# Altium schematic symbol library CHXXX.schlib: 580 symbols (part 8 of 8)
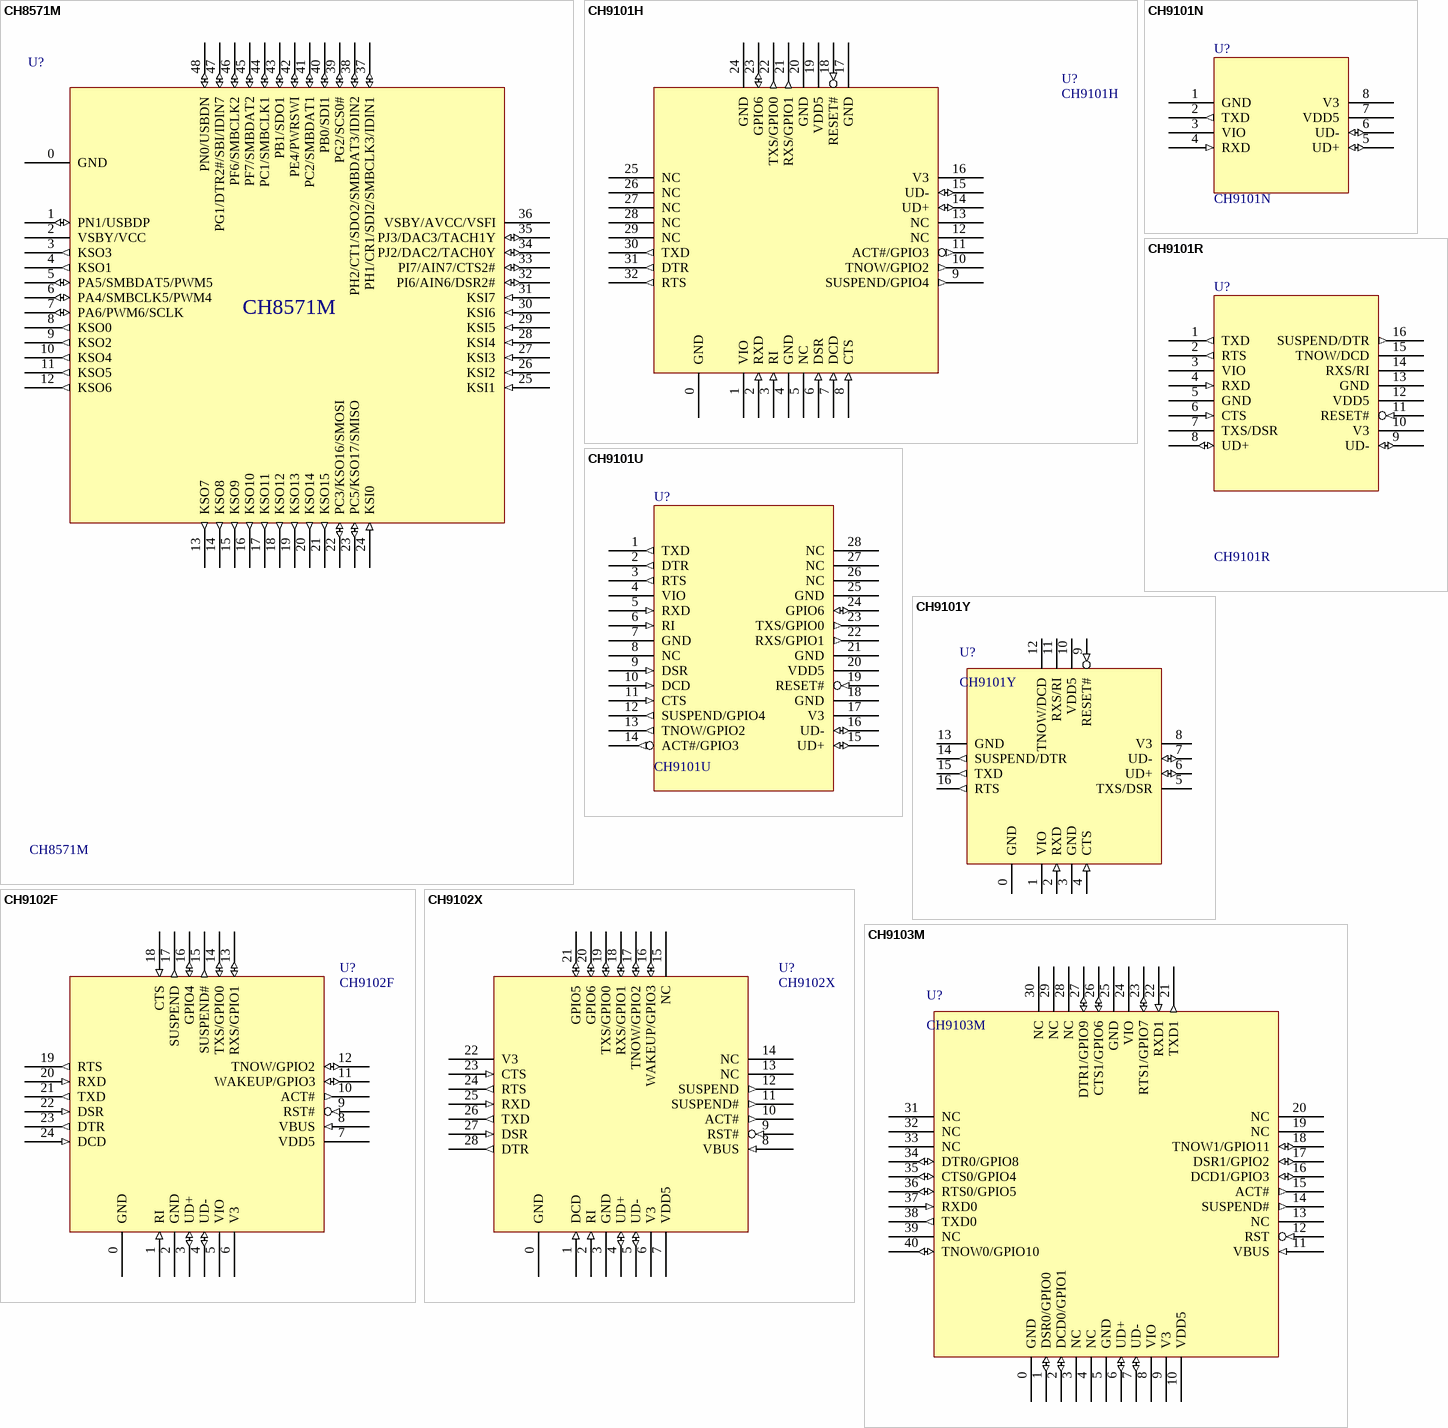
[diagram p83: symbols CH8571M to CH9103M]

## CH9102F
designator U?
USB to high speed TTL Serial / UART
footprint QFN24_4X4
pins: 0 GND (power), 1 RI (in), 2 GND (power), 3 UD+ (io), 4 UD- (io), 5 VIO (power), 6 V3 (power), 7 VDD5 (power), 8 VBUS (in), 9 RST# (in), 10 ACT# (out), 11 WAKEUP/GPIO3 (io), 12 TNOW/GPIO2 (io), 13 RXS/GPIO1 (io), 14 TXS/GPIO0 (io), 15 SUSPEND# (out), 16 GPIO4 (io), 17 SUSPEND (out), 18 CTS (in), 19 RTS (out), 20 RXD (in), 21 TXD (out), 22 DSR (in), 23 DTR (out), 24 DCD (in)

## CH9102X
designator U?
USB to high speed TTL Serial / UART
footprint QFN28_5X5
pins: 0 GND (power), 1 DCD (in), 2 RI (in), 3 GND (power), 4 UD+ (io), 5 UD- (io), 6 V3 (power), 7 VDD5 (power), 8 VBUS (in), 9 RST# (in), 10 ACT# (out), 11 SUSPEND# (out), 12 SUSPEND (out), 13 NC, 14 NC, 15 NC, 16 WAKEUP/GPIO3 (io), 17 TNOW/GPIO2 (io), 18 RXS/GPIO1 (io), 19 TXS/GPIO0 (io), 20 GPIO6 (io), 21 GPIO5 (io), 22 V3 (power), 23 CTS (in), 24 RTS (out), 25 RXD (in), 26 TXD (out), 27 DSR (in), 28 DTR (out)

## CH9103M
designator U?
USB to dual enhanced TTL Serial / 2*UART
footprint QFN40_6X6
pins: 0 GND (power), 1 DSR0/GPIO0 (io), 2 DCD0/GPIO1 (io), 3 NC, 4 NC, 5 GND (power), 6 UD+ (io), 7 UD- (io), 8 VIO (power), 9 V3 (power), 10 VDD5 (power), 11 VBUS (in), 12 RST (in), 13 NC, 14 SUSPEND# (out), 15 ACT# (out), 16 DCD1/GPIO3 (io), 17 DSR1/GPIO2 (io), 18 TNOW1/GPIO11 (io), 19 NC, 20 NC, 21 TXD1 (out), 22 RXD1 (in), 23 RTS1/GPIO7 (io), 24 VIO (power), 25 GND (power), 26 CTS1/GPIO6 (io), 27 DTR1/GPIO9 (io), 28 NC, 29 NC, 30 NC, 31 NC, 32 NC, 33 NC, 34 DTR0/GPIO8 (io), 35 CTS0/GPIO4 (io), 36 RTS0/GPIO5 (io), 37 RXD0 (in), 38 TXD0 (out), 39 NC, 40 TNOW0/GPIO10 (io)

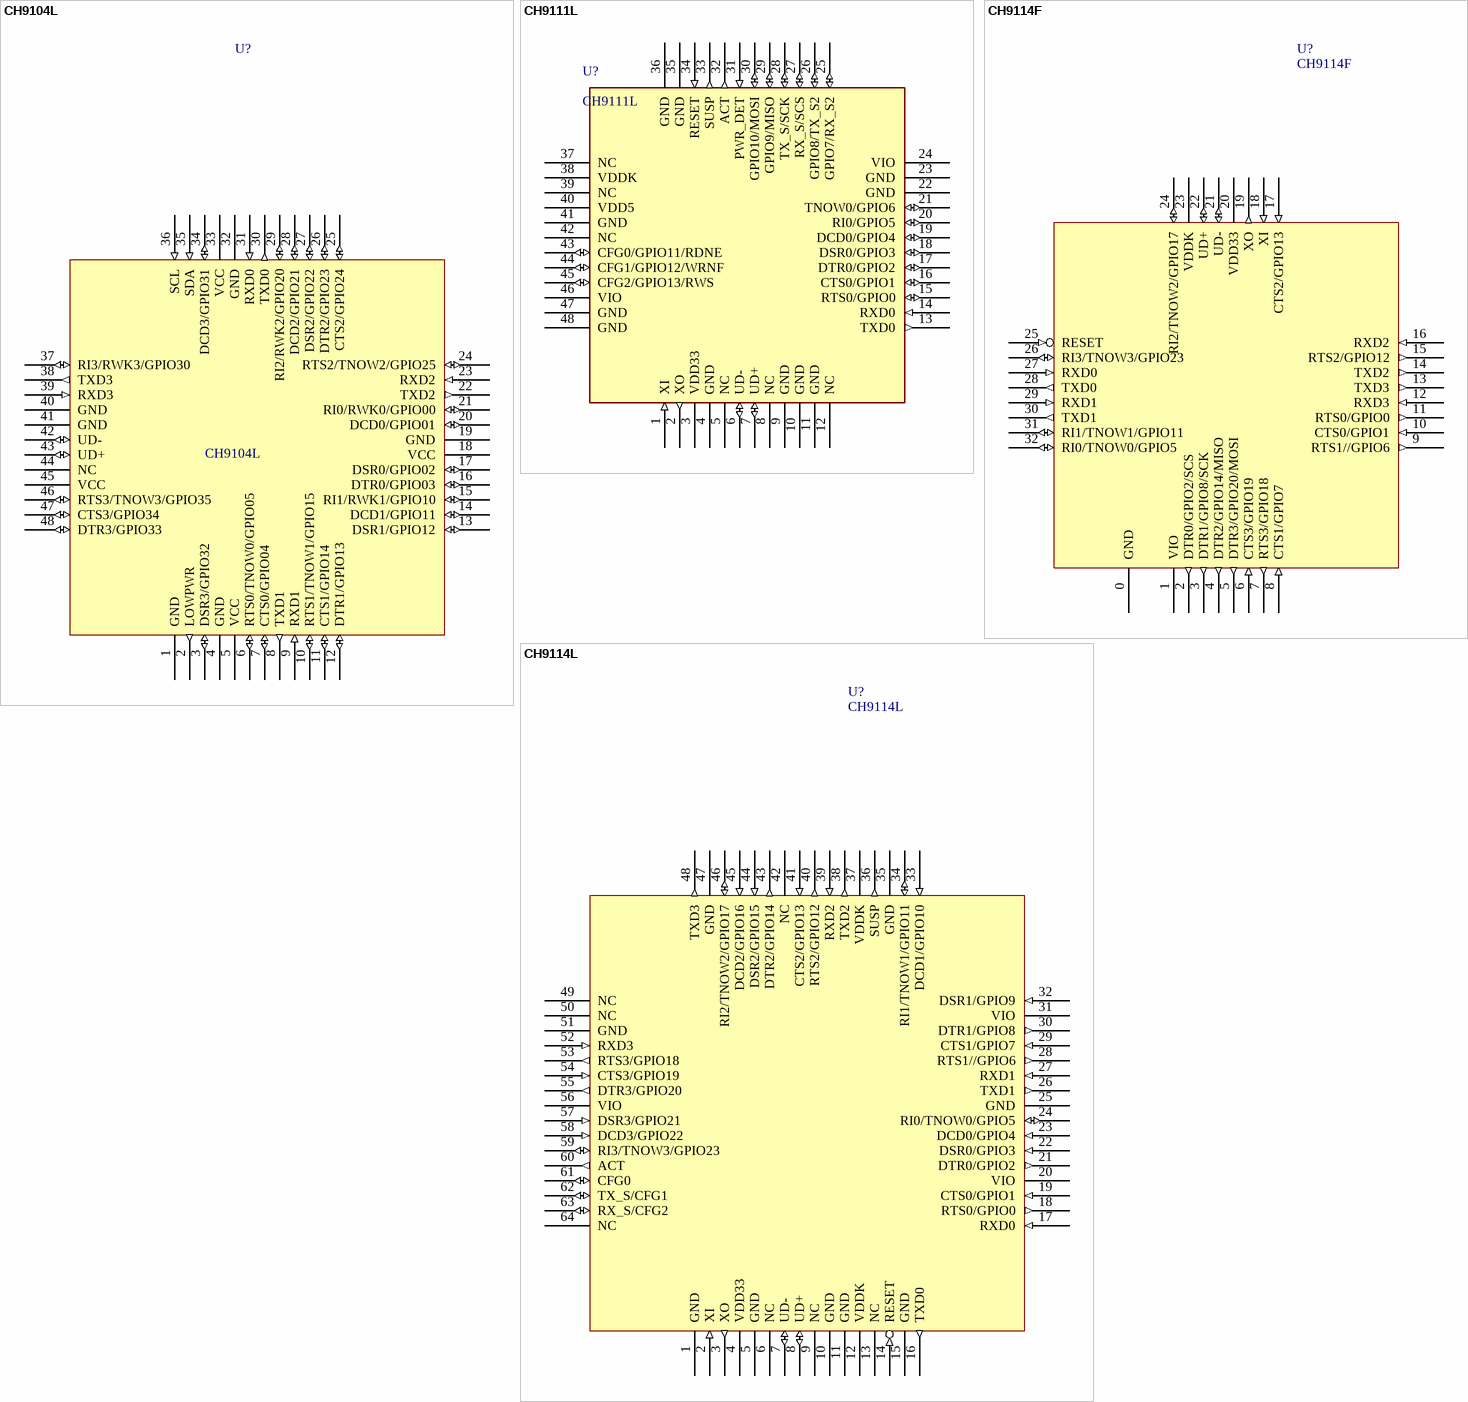
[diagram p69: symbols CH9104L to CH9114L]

## CH9104L
designator U?
USB to quad serial ports / 4*UART
footprint TQFP48_7X7
pins: 1 GND (power), 2 LOWPWR (out), 3 DSR3/GPIO32 (io), 4 GND (power), 5 VCC (power), 6 RTS0/TNOW0/GPIO05 (io), 7 CTS0/GPIO04 (io), 8 TXD1 (out), 9 RXD1 (in), 10 RTS1/TNOW1/GPIO15 (io), 11 CTS1/GPIO14 (io), 12 DTR1/GPIO13 (io), 13 DSR1/GPIO12 (io), 14 DCD1/GPIO11 (io), 15 RI1/RWK1/GPIO10 (io), 16 DTR0/GPIO03 (io), 17 DSR0/GPIO02 (io), 18 VCC (power), 19 GND (power), 20 DCD0/GPIO01 (io), 21 RI0/RWK0/GPIO00 (io), 22 TXD2 (out), 23 RXD2 (in), 24 RTS2/TNOW2/GPIO25 (io), 25 CTS2/GPIO24 (io), 26 DTR2/GPIO23 (io), 27 DSR2/GPIO22 (io), 28 DCD2/GPIO21 (io), 29 RI2/RWK2/GPIO20 (io), 30 TXD0 (out), 31 RXD0 (in), 32 GND (power), 33 VCC (power), 34 DCD3/GPIO31 (io), 35 SDA (in), 36 SCL (in), 37 RI3/RWK3/GPIO30 (io), 38 TXD3 (out), 39 RXD3 (in), 40 GND (power), 41 GND (power), 42 UD- (io), 43 UD+ (io), 44 NC, 45 VCC (power), 46 RTS3/TNOW3/GPIO35 (io), 47 CTS3/GPIO34 (io), 48 DTR3/GPIO33 (io)

## CH9111L
designator U?
High Speed USB to UART
footprint QFN48_7X7
pins: 1 XI (in), 2 XO (out), 3 VDD33 (power), 4 GND (power), 5 NC, 6 UD- (io), 7 UD+ (io), 8 NC, 9 GND (power), 10 GND (power), 11 GND (power), 12 NC, 13 TXD0 (out), 14 RXD0 (in), 15 RTS0/GPIO0 (io), 16 CTS0/GPIO1 (io), 17 DTR0/GPIO2 (io), 18 DSR0/GPIO3 (io), 19 DCD0/GPIO4 (io), 20 RI0/GPIO5 (io), 21 TNOW0/GPIO6 (io), 22 GND (power), 23 GND (power), 24 VIO (power), 25 GPIO7/RX_S2 (io), 26 GPIO8/TX_S2 (io), 27 RX_S/SCS (io), 28 TX_S/SCK (io), 29 GPIO9/MISO (io), 30 GPIO10/MOSI (io), 31 PWR_DET (in), 32 ACT (out), 33 SUSP (out), 34 RESET (in), 35 GND (power), 36 GND (power), 37 NC, 38 VDDK (power), 39 NC, 40 VDD5 (power), 41 GND (power), 42 NC, 43 CFG0/GPIO11/RDNE (io), 44 CFG1/GPIO12/WRNF (io), 45 CFG2/GPIO13/RWS (io), 46 VIO (power), 47 GND (power), 48 GND (power)

## CH9114F
designator U?
high-speed USB to quad UART & SPI
footprint QFN32_4X4
pins: 0 GND (power), 1 VIO (power), 2 DTR0/GPIO2/SCS (out), 3 DTR1/GPIO8/SCK (out), 4 DTR2/GPIO14/MISO (out), 5 DTR3/GPIO20/MOSI (out), 6 CTS3/GPIO19 (in), 7 RTS3/GPIO18 (out), 8 CTS1/GPIO7 (in), 9 RTS1//GPIO6 (out), 10 CTS0/GPIO1 (in), 11 RTS0/GPIO0 (out), 12 RXD3 (in), 13 TXD3 (out), 14 TXD2 (out), 15 RTS2/GPIO12 (out), 16 RXD2 (in), 17 CTS2/GPIO13 (in), 18 XI (in), 19 XO (out), 20 VDD33 (power), 21 UD- (io), 22 UD+ (io), 23 VDDK (power), 24 RI2/TNOW2/GPIO17 (io), 25 RESET (in), 26 RI3/TNOW3/GPIO23 (io), 27 RXD0 (in), 28 TXD0 (out), 29 RXD1 (in), 30 TXD1 (out), 31 RI1/TNOW1/GPIO11 (io), 32 RI0/TNOW0/GPIO5 (io)

## CH9114L
designator U?
high-speed USB to quad UART & dual SPI
footprint LQFP64M_10X10
pins: 1 GND (power), 2 XI (in), 3 XO (out), 4 VDD33 (power), 5 GND (power), 6 NC, 7 UD- (io), 8 UD+ (io), 9 NC, 10 GND (power), 11 GND (power), 12 VDDK (power), 13 NC, 14 RESET (in), 15 GND (power), 16 TXD0 (out), 17 RXD0 (in), 18 RTS0/GPIO0 (out), 19 CTS0/GPIO1 (in), 20 VIO (power), 21 DTR0/GPIO2 (out), 22 DSR0/GPIO3 (in), 23 DCD0/GPIO4 (in), 24 RI0/TNOW0/GPIO5 (io), 25 GND (power), 26 TXD1 (out), 27 RXD1 (in), 28 RTS1//GPIO6 (out), 29 CTS1/GPIO7 (in), 30 DTR1/GPIO8 (out), 31 VIO (power), 32 DSR1/GPIO9 (in), 33 DCD1/GPIO10 (in), 34 RI1/TNOW1/GPIO11 (io), 35 GND (power), 36 SUSP (out), 37 VDDK (power), 38 TXD2 (out), 39 RXD2 (in), 40 RTS2/GPIO12 (out), 41 CTS2/GPIO13 (in), 42 NC, 43 DTR2/GPIO14 (out), 44 DSR2/GPIO15 (in), 45 DCD2/GPIO16 (in), 46 RI2/TNOW2/GPIO17 (io), 47 GND (power), 48 TXD3 (out), 49 NC, 50 NC, 51 GND (power), 52 RXD3 (in), 53 RTS3/GPIO18 (out), 54 CTS3/GPIO19 (in), 55 DTR3/GPIO20 (out), 56 VIO (power), 57 DSR3/GPIO21 (in), 58 DCD3/GPIO22 (in), 59 RI3/TNOW3/GPIO23 (io), 60 ACT (out), 61 CFG0 (io), 62 TX_S/CFG1 (io), 63 RX_S/CFG2 (io), 64 NC

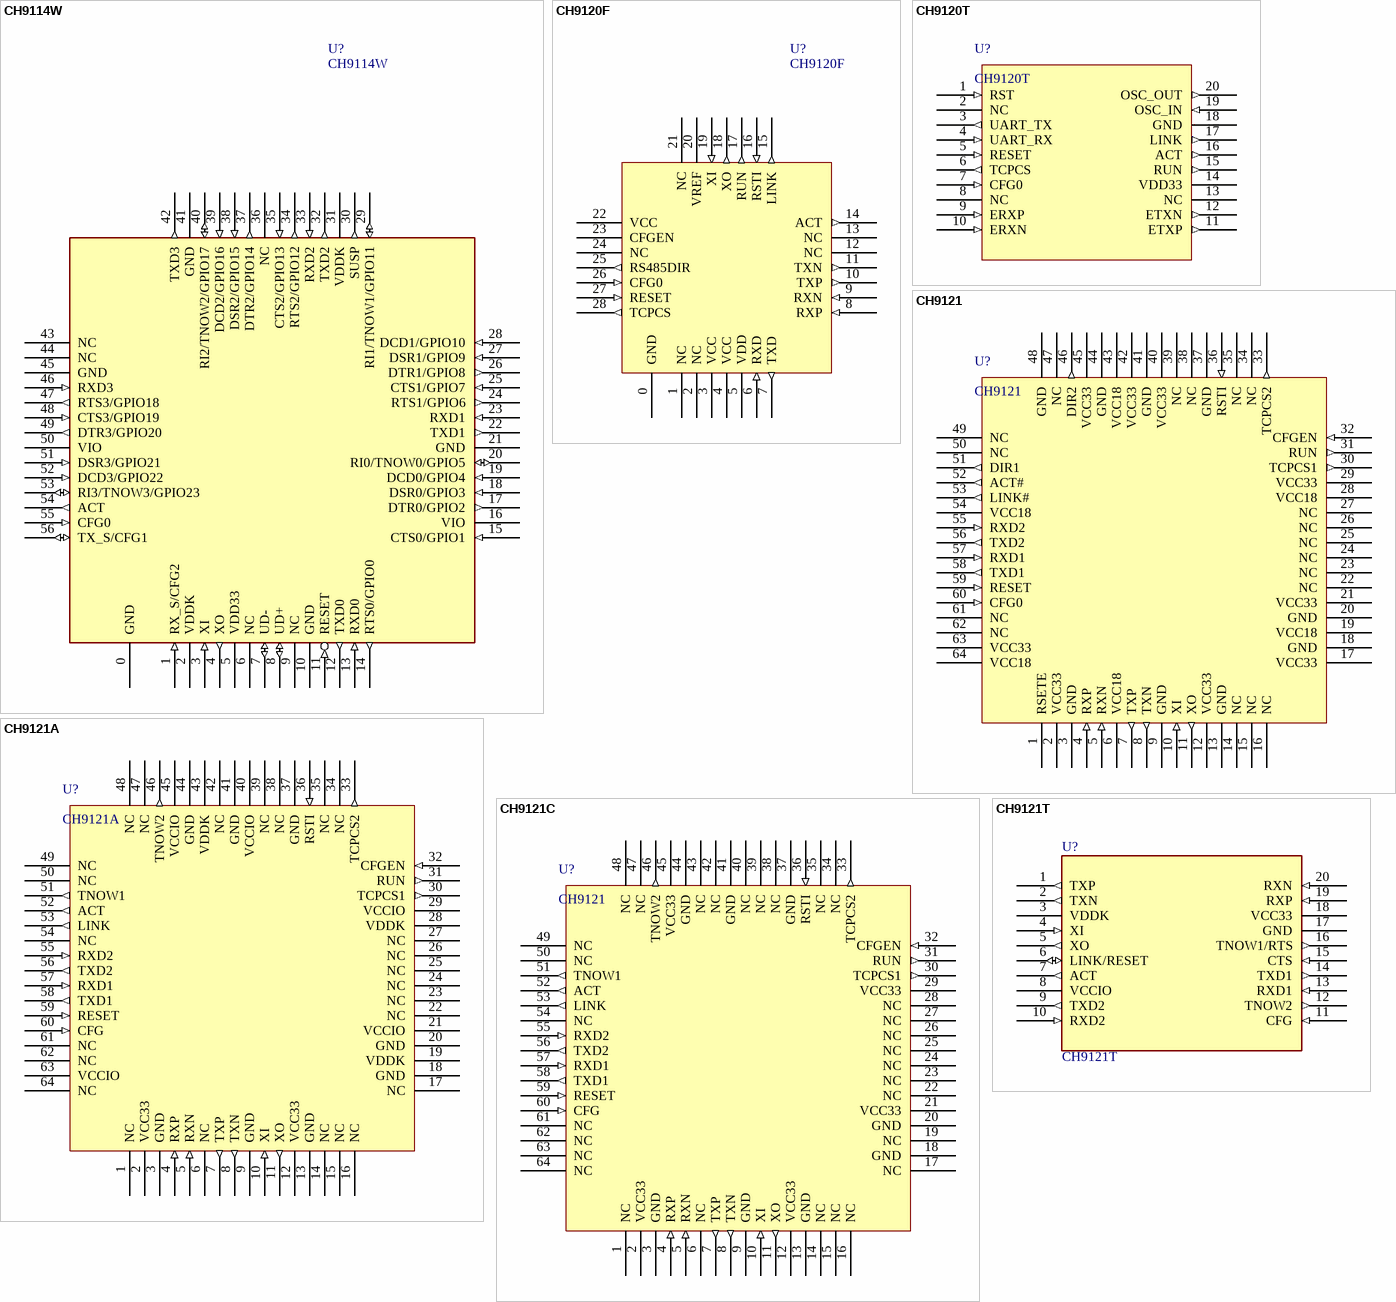
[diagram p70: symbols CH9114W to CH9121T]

## CH9114W
designator U?
high-speed USB to quad UART & dual SPI
footprint QFN56_8X8
pins: 0 GND (power), 1 RX_S/CFG2 (in), 2 VDDK (power), 3 XI (in), 4 XO (out), 5 VDD33 (power), 6 NC, 7 UD- (io), 8 UD+ (io), 9 NC, 10 GND (power), 11 RESET (in), 12 TXD0 (out), 13 RXD0 (in), 14 RTS0/GPIO0 (out), 15 CTS0/GPIO1 (in), 16 VIO (power), 17 DTR0/GPIO2 (out), 18 DSR0/GPIO3 (in), 19 DCD0/GPIO4 (in), 20 RI0/TNOW0/GPIO5 (io), 21 GND (power), 22 TXD1 (out), 23 RXD1 (in), 24 RTS1/GPIO6 (out), 25 CTS1/GPIO7 (in), 26 DTR1/GPIO8 (out), 27 DSR1/GPIO9 (in), 28 DCD1/GPIO10 (in), 29 RI1/TNOW1/GPIO11 (io), 30 SUSP (out), 31 VDDK (power), 32 TXD2 (out), 33 RXD2 (in), 34 RTS2/GPIO12 (out), 35 CTS2/GPIO13 (in), 36 NC, 37 DTR2/GPIO14 (out), 38 DSR2/GPIO15 (in), 39 DCD2/GPIO16 (in), 40 RI2/TNOW2/GPIO17 (io), 41 GND (power), 42 TXD3 (out), 43 NC, 44 NC, 45 GND (power), 46 RXD3 (in), 47 RTS3/GPIO18 (out), 48 CTS3/GPIO19 (in), 49 DTR3/GPIO20 (out), 50 VIO (power), 51 DSR3/GPIO21 (in), 52 DCD3/GPIO22 (in), 53 RI3/TNOW3/GPIO23 (io), 54 ACT (out), 55 CFG0 (in), 56 TX_S/CFG1 (io)

## CH9120F
designator U?
TTL serail / UART to 10Mbps ethernet
footprint QFN28_4X4
pins: 0 GND (power), 1 NC, 2 NC, 3 VCC (power), 4 VCC (power), 5 VDD (power), 6 RXD (in), 7 TXD (out), 8 RXP (in), 9 RXN (in), 10 TXP (out), 11 TXN (out), 12 NC, 13 NC, 14 ACT (out), 15 LINK (out), 16 RSTI (in), 17 RUN (out), 18 XO (out), 19 XI (in), 20 VREF (power), 21 NC, 22 VCC (power), 23 CFGEN, 24 NC, 25 RS485DIR (out), 26 CFG0 (in), 27 RESET (in), 28 TCPCS (out)

## CH9120T
designator U?
TTL serail / UART to 10Mbps ethernet
footprint TSSOP20
pins: 1 RST (in), 2 NC, 3 UART_TX (out), 4 UART_RX (in), 5 RESET (in), 6 TCPCS (out), 7 CFG0 (in), 8 NC, 9 ERXP (in), 10 ERXN (in), 11 ETXP (out), 12 ETXN (out), 13 NC, 14 VDD33 (power), 15 RUN (out), 16 ACT (out), 17 LINK (out), 18 GND (power), 19 OSC_IN (in), 20 OSC_OUT (out)

## CH9121
designator U?
dual TTL serail / 2*UART to 10Mbps/100Mbps Ethernet
footprint LQFP64M_10X10
pins: 1 RSETE, 2 VCC33 (power), 3 GND, 4 RXP (in), 5 RXN (in), 6 VCC18 (power), 7 TXP (out), 8 TXN (out), 9 GND (power), 10 XI (in), 11 XO (out), 12 VCC33 (power), 13 GND (power), 14 NC, 15 NC, 16 NC, 17 VCC33 (power), 18 GND (power), 19 VCC18 (power), 20 GND (power), 21 VCC33 (power), 22 NC, 23 NC, 24 NC, 25 NC, 26 NC, 27 NC, 28 VCC18 (power), 29 VCC33 (power), 30 TCPCS1 (out), 31 RUN (out), 32 CFGEN (in), 33 TCPCS2 (out), 34 NC, 35 NC, 36 RSTI (in), 37 GND (power), 38 NC, 39 NC, 40 VCC33 (power), 41 GND (power), 42 VCC33 (power), 43 VCC18 (power), 44 GND (power), 45 VCC33 (power), 46 DIR2 (out), 47 NC, 48 GND (power), 49 NC, 50 NC, 51 DIR1 (out), 52 ACT# (out), 53 LINK# (out), 54 VCC18 (power), 55 RXD2 (in), 56 TXD2 (out), 57 RXD1 (in), 58 TXD1 (out), 59 RESET (in), 60 CFG0 (in), 61 NC, 62 NC, 63 VCC33 (power), 64 VCC18 (power)

## CH9121A
designator U?
dual TTL serail / 2*UART to 10Mbps/100Mbps Ethernet
footprint LQFP64M_10X10
pins: 1 NC, 2 VCC33 (power), 3 GND, 4 RXP (in), 5 RXN (in), 6 NC (power), 7 TXP (out), 8 TXN (out), 9 GND (power), 10 XI (in), 11 XO (out), 12 VCC33 (power), 13 GND (power), 14 NC, 15 NC, 16 NC, 17 NC (power), 18 GND (power), 19 VDDK (power), 20 GND (power), 21 VCCIO (power), 22 NC, 23 NC, 24 NC, 25 NC, 26 NC, 27 NC, 28 VDDK (power), 29 VCCIO (power), 30 TCPCS1 (out), 31 RUN (out), 32 CFGEN (in), 33 TCPCS2 (out), 34 NC, 35 NC, 36 RSTI (in), 37 GND (power), 38 NC, 39 NC, 40 VCCIO (power), 41 GND (power), 42 NC (power), 43 VDDK (power), 44 GND (power), 45 VCCIO (power), 46 TNOW2 (out), 47 NC, 48 NC (power), 49 NC, 50 NC, 51 TNOW1 (out), 52 ACT (out), 53 LINK (out), 54 NC (power), 55 RXD2 (in), 56 TXD2 (out), 57 RXD1 (in), 58 TXD1 (out), 59 RESET (in), 60 CFG (in), 61 NC, 62 NC, 63 VCCIO (power), 64 NC (power)

## CH9121C
designator U?, comment CH9121
dual TTL serail / 2*UART to 10Mbps/100Mbps Ethernet
footprint LQFP64M_10X10
pins: 1 NC, 2 VCC33 (power), 3 GND, 4 RXP (in), 5 RXN (in), 6 NC, 7 TXP (out), 8 TXN (out), 9 GND (power), 10 XI (in), 11 XO (out), 12 VCC33 (power), 13 GND (power), 14 NC, 15 NC, 16 NC, 17 NC (power), 18 GND (power), 19 NC (power), 20 GND (power), 21 VCC33 (power), 22 NC, 23 NC, 24 NC, 25 NC, 26 NC, 27 NC, 28 NC, 29 VCC33 (power), 30 TCPCS1 (out), 31 RUN (out), 32 CFGEN (in), 33 TCPCS2 (out), 34 NC, 35 NC, 36 RSTI (in), 37 GND (power), 38 NC, 39 NC, 40 NC, 41 GND (power), 42 NC (power), 43 NC, 44 GND (power), 45 VCC33 (power), 46 TNOW2 (out), 47 NC, 48 NC (power), 49 NC, 50 NC, 51 TNOW1 (out), 52 ACT (out), 53 LINK (out), 54 NC (power), 55 RXD2 (in), 56 TXD2 (out), 57 RXD1 (in), 58 TXD1 (out), 59 RESET (in), 60 CFG (in), 61 NC, 62 NC, 63 NC, 64 NC (power)

## CH9121T
designator U?
Network and UART Transparent Transmission on 100M Ethernet
footprint TSSOP20
pins: 1 TXP (out), 2 TXN (out), 3 VDDK, 4 XI (in), 5 XO (out), 6 LINK/RESET (io), 7 ACT (out), 8 VCCIO, 9 TXD2 (out), 10 RXD2 (in), 11 CFG (in), 12 TNOW2 (out), 13 RXD1 (in), 14 TXD1 (out), 15 CTS (in), 16 TNOW1/RTS (out), 17 GND, 18 VCC33, 19 RXP (in), 20 RXN (in)

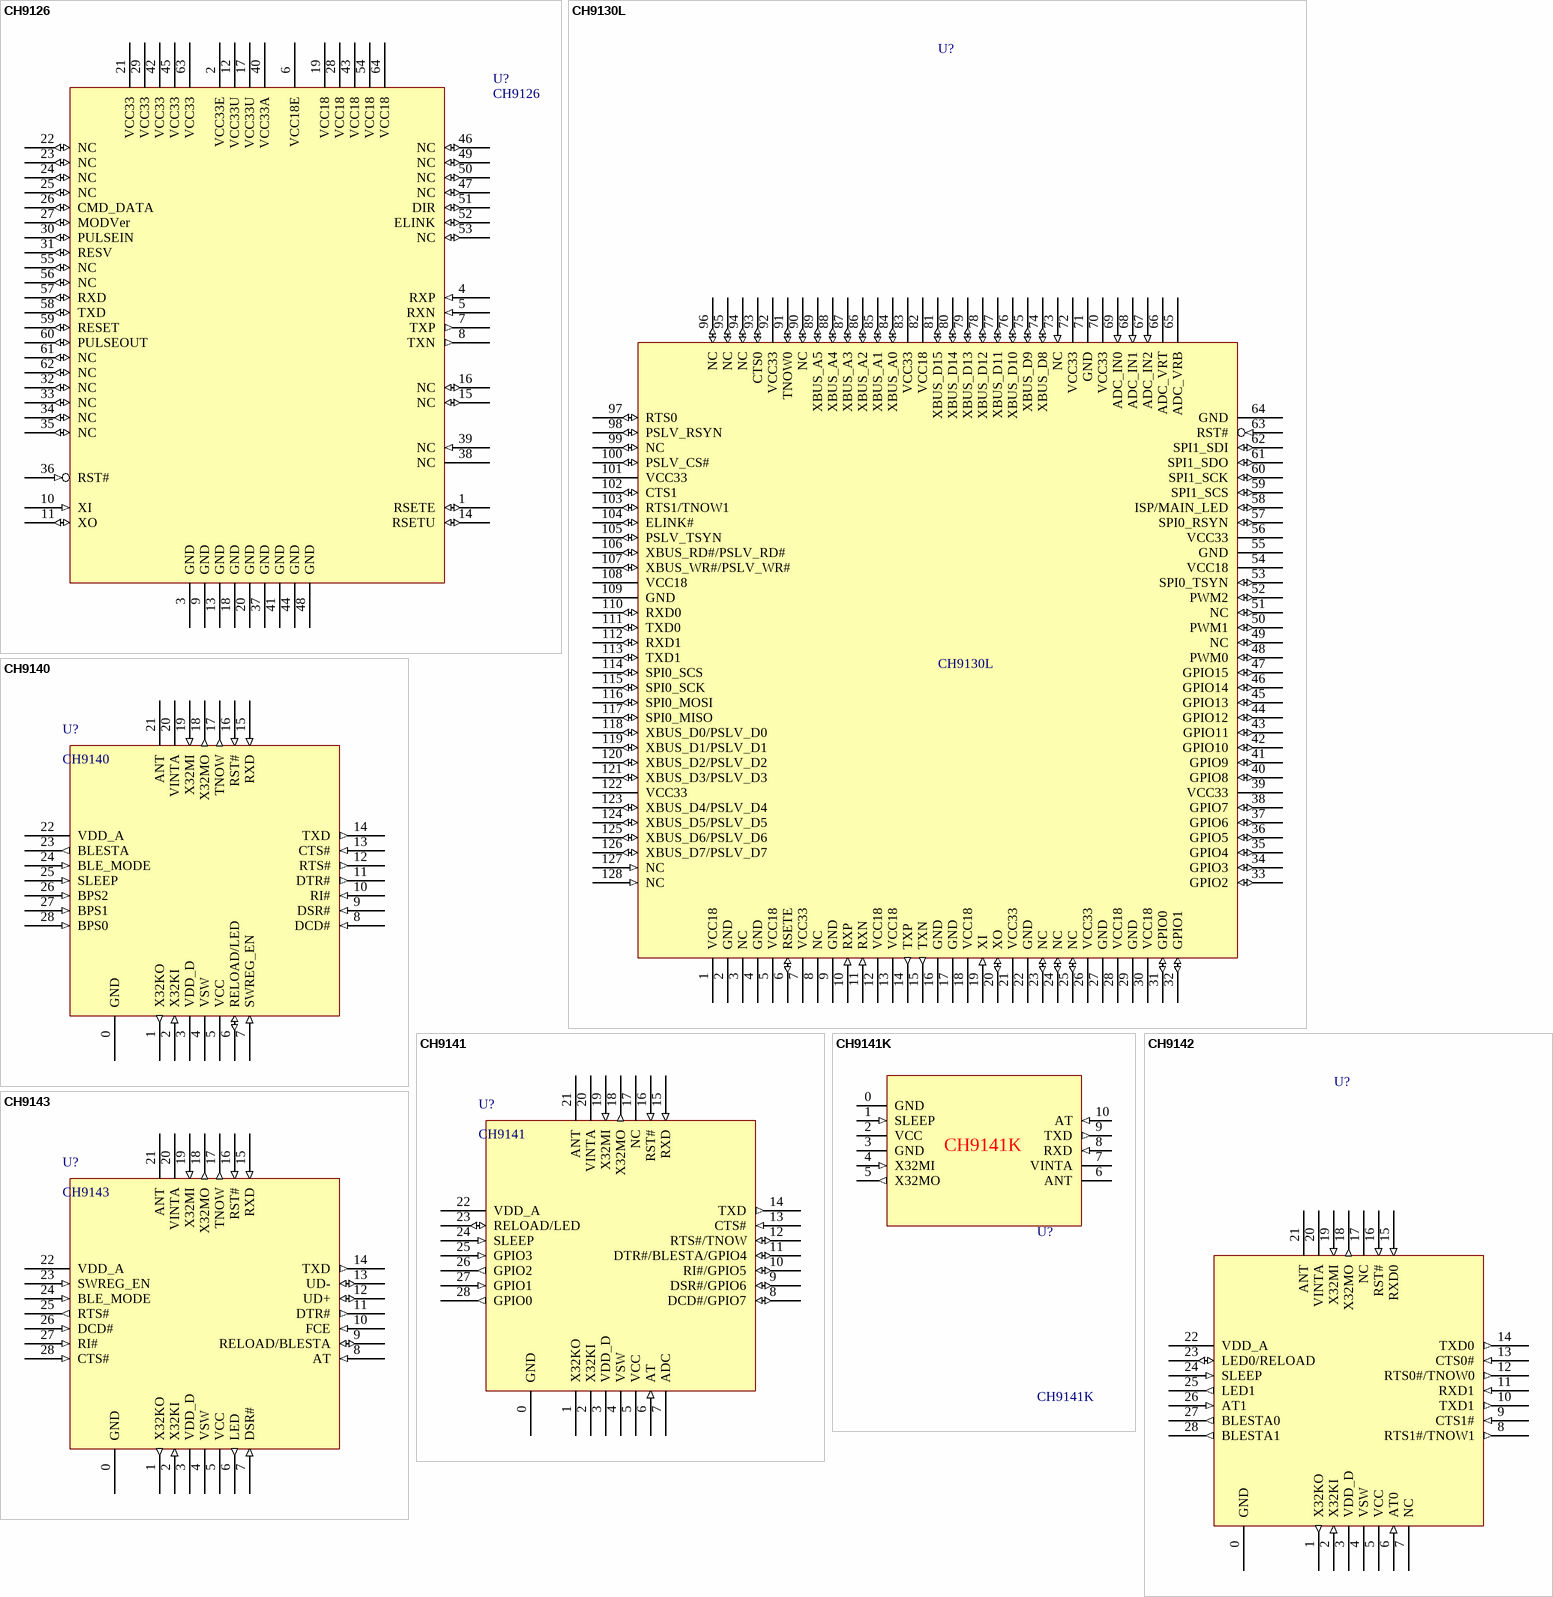
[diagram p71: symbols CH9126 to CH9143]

## CH9126
designator U?
SNTP via 100Mbps Ethernet
footprint LQFP64M_10X10
pins: 1 RSETE (io), 2 VCC33E (power), 3 GND (power), 4 RXP (in), 5 RXN (in), 6 VCC18E (power), 7 TXP (out), 8 TXN (out), 9 GND (power), 10 XI (in), 11 XO (io), 12 VCC33U (power), 13 GND (power), 14 RSETU (io), 15 NC (io), 16 NC (io), 17 VCC33U (power), 18 GND (power), 19 VCC18 (power), 20 GND (power), 21 VCC33 (power), 22 NC (io), 23 NC (io), 24 NC (io), 25 NC (io), 26 CMD_DATA (io), 27 MODVer (io), 28 VCC18 (power), 29 VCC33 (power), 30 PULSEIN (io), 31 RESV (io), 32 NC (io), 33 NC (io), 34 NC (io), 35 NC (io), 36 RST# (in), 37 GND (power), 38 NC (power), 39 NC (in), 40 VCC33A (power), 41 GND (power), 42 VCC33 (power), 43 VCC18 (power), 44 GND (power), 45 VCC33 (power), 46 NC (io), 47 NC (io), 48 GND (power), 49 NC (io), 50 NC (io), 51 DIR (io), 52 ELINK (io), 53 NC (io), 54 VCC18 (power), 55 NC (io), 56 NC (io), 57 RXD (io), 58 TXD (io), 59 RESET (io), 60 PULSEOUT (io), 61 NC (io), 62 NC (io), 63 VCC33 (power), 64 VCC18 (power)

## CH9130L
designator U?
remote UART/SPI/GPIO/ADC/PWM/parallel via 100Mbps Ethernet
footprint LQFP128
pins: 1 VCC18 (power), 2 GND (power), 3 NC, 4 GND (power), 5 VCC18 (power), 6 RSETE (io), 7 VCC33 (power), 8 NC, 9 GND (power), 10 RXP (in), 11 RXN (in), 12 VCC18 (power), 13 VCC18 (power), 14 TXP (out), 15 TXN (out), 16 GND (power), 17 GND (power), 18 VCC18 (power), 19 XI (in), 20 XO (io), 21 VCC33 (power), 22 GND (power), 23 NC (io), 24 NC (io), 25 NC (io), 26 VCC33 (power), 27 GND (power), 28 VCC18 (power), 29 GND (power), 30 VCC18 (power), 31 GPIO0 (io), 32 GPIO1 (io), 33 GPIO2 (io), 34 GPIO3 (io), 35 GPIO4 (io), 36 GPIO5 (io), 37 GPIO6 (io), 38 GPIO7 (io), 39 VCC33 (power), 40 GPIO8 (io), 41 GPIO9 (io), 42 GPIO10 (io), 43 GPIO11 (io), 44 GPIO12 (io), 45 GPIO13 (io), 46 GPIO14 (io), 47 GPIO15 (io), 48 PWM0 (io), 49 NC (io), 50 PWM1 (io), 51 NC (io), 52 PWM2 (io), 53 SPI0_TSYN (io), 54 VCC18 (power), 55 GND (power), 56 VCC33 (power), 57 SPI0_RSYN (io), 58 ISP/MAIN_LED (io), 59 SPI1_SCS (io), 60 SPI1_SCK (io), 61 SPI1_SDO (io), 62 SPI1_SDI (io), 63 RST# (in), 64 GND (power), 65 ADC_VRB (power), 66 ADC_VRT (power), 67 ADC_IN2 (in), 68 ADC_IN1 (in), 69 ADC_IN0 (in), 70 VCC33 (power), 71 GND (power), 72 VCC33 (power), 73 NC (in), 74 XBUS_D8 (io), 75 XBUS_D9 (io), 76 XBUS_D10 (io), 77 XBUS_D11 (io), 78 XBUS_D12 (io), 79 XBUS_D13 (io), 80 XBUS_D14 (io), 81 XBUS_D15 (io), 82 VCC18 (power), 83 VCC33 (power), 84 XBUS_A0 (io), 85 XBUS_A1 (io), 86 XBUS_A2 (io), 87 XBUS_A3 (io), 88 XBUS_A4 (io), 89 XBUS_A5 (io), 90 NC (io), 91 TNOW0 (io), 92 VCC33 (power), 93 CTS0 (io), 94 NC (io), 95 NC (io), 96 NC (io), 97 RTS0 (io), 98 PSLV_RSYN (io), 99 NC (io), 100 PSLV_CS# (io), 101 VCC33 (power), 102 CTS1 (io), 103 RTS1/TNOW1 (io), 104 ELINK# (io), 105 PSLV_TSYN (io), 106 XBUS_RD#/PSLV_RD# (io), 107 XBUS_WR#/PSLV_WR# (io), 108 VCC18 (power), 109 GND (power), 110 RXD0 (io), 111 TXD0 (io), 112 RXD1 (io), 113 TXD1 (io), 114 SPI0_SCS (io), 115 SPI0_SCK (io), 116 SPI0_MOSI (io), 117 SPI0_MISO (io), 118 XBUS_D0/PSLV_D0 (io), 119 XBUS_D1/PSLV_D1 (io), 120 XBUS_D2/PSLV_D2 (io), 121 XBUS_D3/PSLV_D3 (io), 122 VCC33 (power), 123 XBUS_D4/PSLV_D4 (io), 124 XBUS_D5/PSLV_D5 (io), 125 XBUS_D6/PSLV_D6 (io), 126 XBUS_D7/PSLV_D7 (io), 127 NC (in), 128 NC (in)

## CH9140
designator U?
Bluetooth-LowEnergy to UART
footprint QFN28_4X4
pins: 0 GND (power), 1 X32KO (out), 2 X32KI (in), 3 VDD_D (power), 4 VSW (power), 5 VCC (power), 6 RELOAD/LED (io), 7 SWREG_EN (in), 8 DCD# (in), 9 DSR# (in), 10 RI# (in), 11 DTR# (out), 12 RTS# (out), 13 CTS# (in), 14 TXD (out), 15 RXD (in), 16 RST# (in), 17 TNOW (out), 18 X32MO (out), 19 X32MI (in), 20 VINTA (power), 21 ANT, 22 VDD_A (power), 23 BLESTA (out), 24 BLE_MODE (in), 25 SLEEP (in), 26 BPS2 (in), 27 BPS1 (in), 28 BPS0 (in)

## CH9141
designator U?
Bluetooth-LowEnergy & UART Mutual Transport
footprint QFN28_4X4
pins: 0 GND (power), 1 X32KO, 2 X32KI, 3 VDD_D (power), 4 VSW (power), 5 VCC (power), 6 AT (in), 7 ADC, 8 DCD#/GPIO7 (io), 9 DSR#/GPIO6 (io), 10 RI#/GPIO5 (io), 11 DTR#/BLESTA/GPIO4 (io), 12 RTS#/TNOW (io), 13 CTS# (in), 14 TXD (out), 15 RXD (in), 16 RST# (in), 17 NC (hiz), 18 X32MO (out), 19 X32MI (in), 20 VINTA (power), 21 ANT, 22 VDD_A (power), 23 RELOAD/LED (io), 24 SLEEP (in), 25 GPIO3 (in), 26 GPIO2 (out), 27 GPIO1 (in), 28 GPIO0 (out)

## CH9141K
designator U?
Bluetooth-LowEnergy & UART Mutual Transport
footprint ESSOP10
pins: 0 GND (power), 1 SLEEP (in), 2 VCC (power), 3 GND (power), 4 X32MI (in), 5 X32MO (out), 6 ANT (power), 7 VINTA (power), 8 RXD (in), 9 TXD (out), 10 AT (in)

## CH9142
designator U?  (value not drawn)
Bluetooth-LowEnergy & Double UART Mutual Transport
footprint QFN28_4X4
pins: 0 GND (power), 1 X32KO (out), 2 X32KI (in), 3 VDD_D (power), 4 VSW (power), 5 VCC (power), 6 AT0 (in), 7 NC, 8 RTS1#/TNOW1 (out), 9 CTS1# (in), 10 TXD1 (out), 11 RXD1 (in), 12 RTS0#/TNOW0 (out), 13 CTS0# (in), 14 TXD0 (out), 15 RXD0 (in), 16 RST# (in), 17 NC, 18 X32MO (out), 19 X32MI (in), 20 VINTA (power), 21 ANT, 22 VDD_A (power), 23 LED0/RELOAD (io), 24 SLEEP (in), 25 LED1 (out), 26 AT1 (in), 27 BLESTA0 (out), 28 BLESTA1 (out)

## CH9143
designator U?
Bluetooth-LowEnergy & UART & USB Mutual Transport
footprint QFN28_4X4
pins: 0 GND (power), 1 X32KO (out), 2 X32KI (in), 3 VDD_D (power), 4 VSW (power), 5 VCC (power), 6 LED (out), 7 DSR# (in), 8 AT (in), 9 RELOAD/BLESTA (io), 10 FCE (in), 11 DTR# (out), 12 UD+ (io), 13 UD- (io), 14 TXD (out), 15 RXD (in), 16 RST# (in), 17 TNOW (out), 18 X32MO (out), 19 X32MI (in), 20 VINTA (power), 21 ANT, 22 VDD_A (power), 23 SWREG_EN (in), 24 BLE_MODE (in), 25 RTS# (out), 26 DCD# (in), 27 RI# (in), 28 CTS# (in)

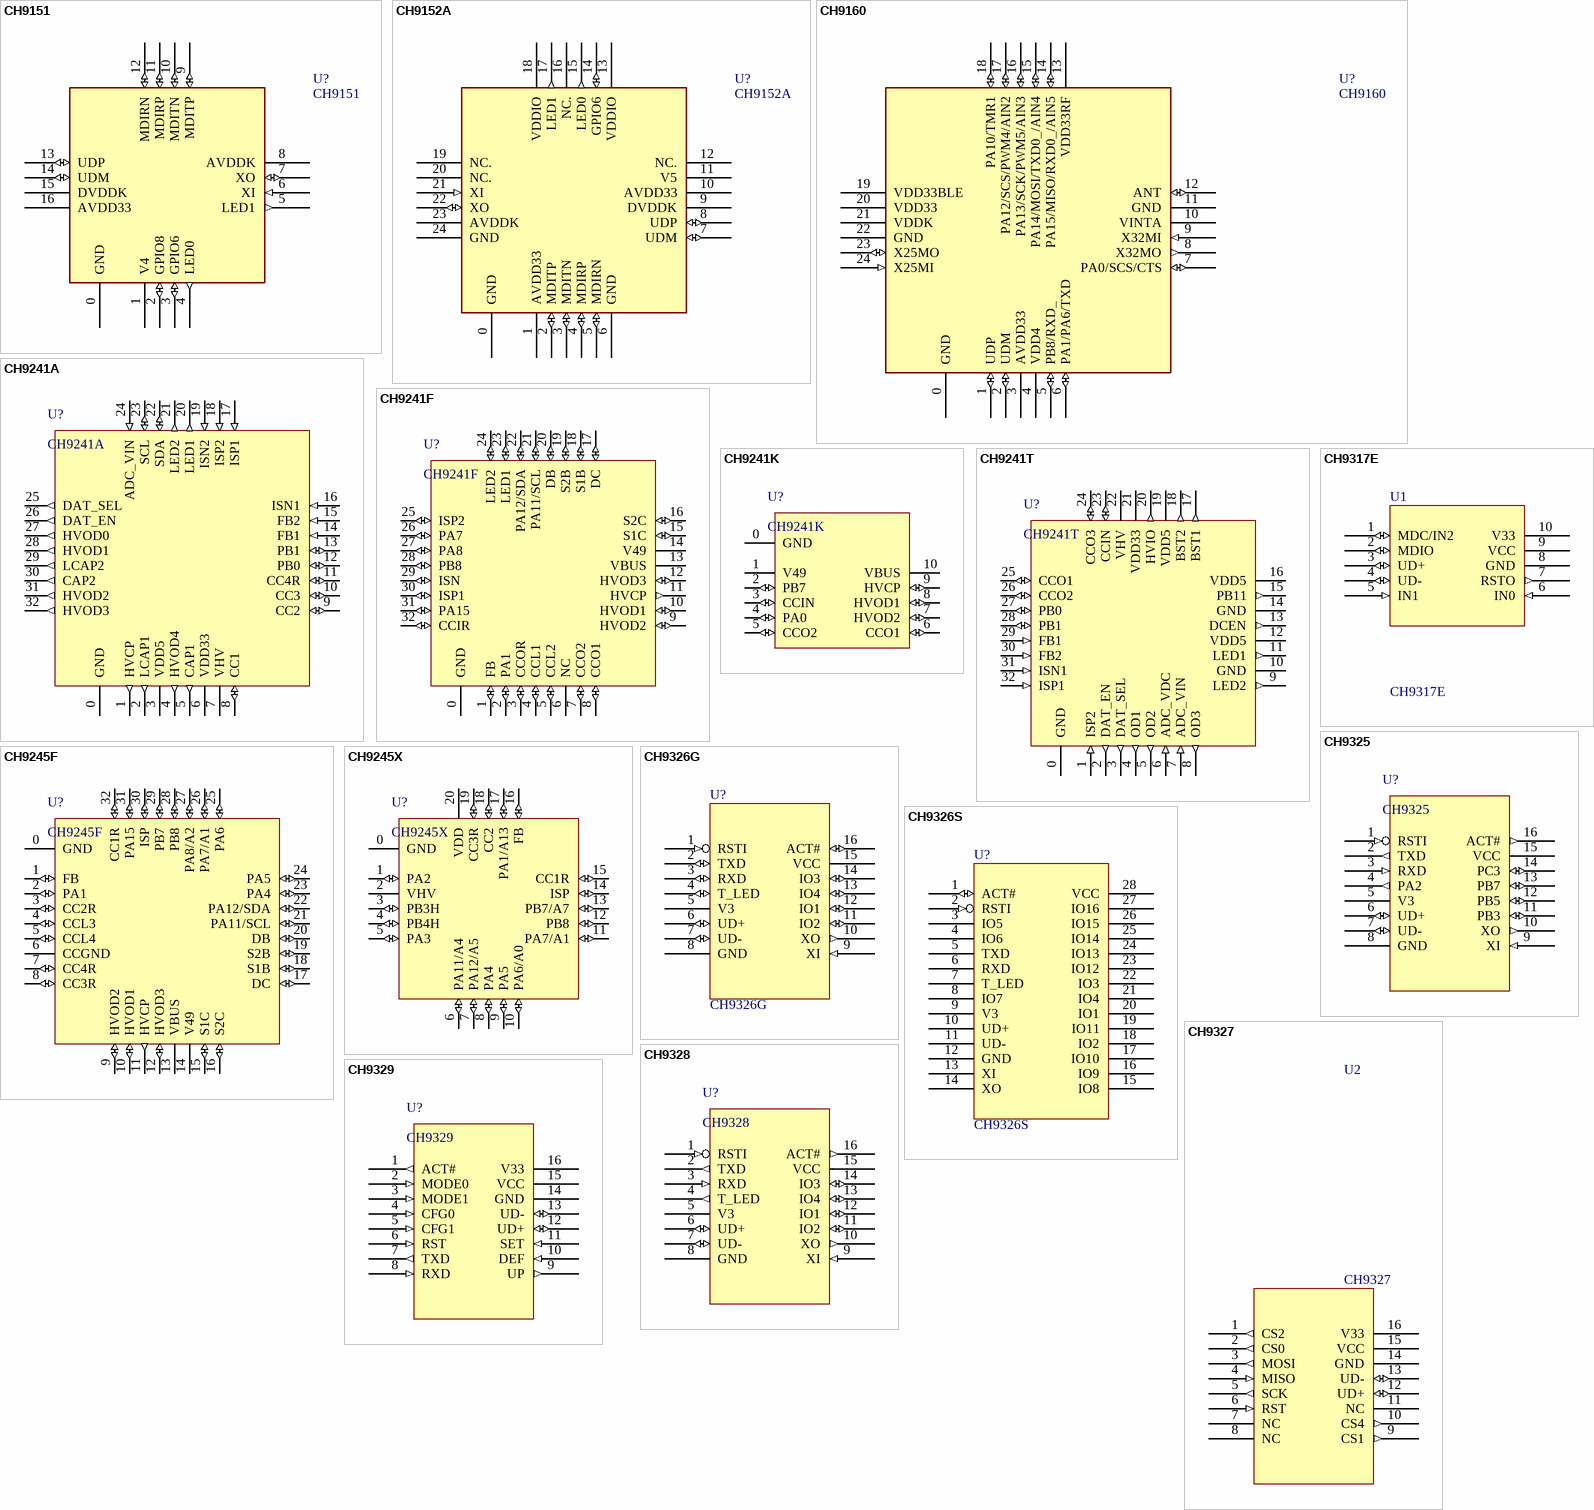
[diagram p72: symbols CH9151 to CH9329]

## CH9151
designator U?
USB2.0 to 10/100M Fast Ethernet with Driver Flash
footprint QFN16_3X3
pins: 0 GND (power), 1 V4 (power), 2 GPIO8 (io), 3 GPIO6 (io), 4 LED0 (out), 5 LED1 (out), 6 XI (in), 7 XO (io), 8 AVDDK (power), 9 MDITP (io), 10 MDITN (io), 11 MDIRP (io), 12 MDIRN (io), 13 UDP (io), 14 UDM (io), 15 DVDDK (power), 16 AVDD33 (power)

## CH9152A
designator U?
USB2.0 to 10/100M Fast Ethernet with Driver Flash
footprint QFN24_4X4
pins: 0 GND (power), 1 AVDD33 (power), 2 MDITP (io), 3 MDITN (io), 4 MDIRP (io), 5 MDIRN (io), 6 GND (power), 7 UDM (io), 8 UDP (io), 9 DVDDK (power), 10 AVDD33 (power), 11 V5 (power), 12 NC., 13 VDDIO (power), 14 GPIO6 (io), 15 LED0 (out), 16 NC., 17 LED1 (out), 18 VDDIO (power), 19 NC., 20 NC., 21 XI (in), 22 XO (io), 23 AVDDK (power), 24 GND (power)

## CH9160
designator U?
BLE to USB2.0 high speed HID
footprint QFN24_4X4 (Footprint not found)
pins: 0 GND (power), 1 UDP (io), 2 UDM (io), 3 AVDD33 (power), 4 VDD4 (power), 5 PB8/RXD_ (io), 6 PA1/PA6/TXD (io), 7 PA0/SCS/CTS (io), 8 X32MO (out), 9 X32MI (in), 10 VINTA (power), 11 GND (power), 12 ANT (io), 13 VDD33RF (power), 14 PA15/MISO/RXD0_/AIN5 (io), 15 PA14/MOSI/TXD0_/AIN4 (io), 16 PA13/SCK/PWM5/AIN3 (io), 17 PA12/SCS/PWM4/AIN2 (io), 18 PA10/TMR1 (io), 19 VDD33BLE (power), 20 VDD33 (power), 21 VDDK (power), 22 GND (power), 23 X25MO (io), 24 X25MI (in)

## CH9241A
designator U?
RISC-V MCU & USB PD & Type-C & Fast Charge Power Consumer Controller
footprint QFN32_4X4
pins: 0 GND (power), 1 HVCP (out), 2 LCAP1 (out), 3 VDD5 (power), 4 HVOD4 (out), 5 CAP1 (out), 6 VDD33 (power), 7 VHV (power), 8 CC1 (io), 9 CC2 (io), 10 CC3 (io), 11 CC4R (io), 12 PB0 (io), 13 PB1 (io), 14 FB1 (in), 15 FB2 (in), 16 ISN1 (in), 17 ISP1 (in), 18 ISP2 (in), 19 ISN2 (in), 20 LED1 (out), 21 LED2 (out), 22 SDA (io), 23 SCL (io), 24 ADC_VIN (in), 25 DAT_SEL (out), 26 DAT_EN (out), 27 HVOD0 (out), 28 HVOD1 (out), 29 LCAP2 (out), 30 CAP2 (out), 31 HVOD2 (out), 32 HVOD3 (out)

## CH9241F
designator U?
RISC-V MCU & USB PD & Type-C & Fast Charge Power Consumer Controller
footprint QFN32_4X4
pins: 0 GND (power), 1 FB (io), 2 PA1 (io), 3 CCOR (io), 4 CCL1 (io), 5 CCL2 (io), 6 NC, 7 CCO2 (io), 8 CCO1 (io), 9 HVOD2 (io), 10 HVOD1 (io), 11 HVCP (out), 12 HVOD3 (io), 13 VBUS (power), 14 V49 (power), 15 S1C (io), 16 S2C (io), 17 DC (io), 18 S1B (io), 19 S2B (io), 20 DB (io), 21 PA11/SCL (io), 22 PA12/SDA (io), 23 LED1 (io), 24 LED2 (io), 25 ISP2 (io), 26 PA7 (io), 27 PA8 (io), 28 PB8 (io), 29 ISN (io), 30 ISP1 (io), 31 PA15 (io), 32 CCIR (io)

## CH9241K
designator U?
RISC-V MCU & USB PD & Type-C & Fast Charge Power Consumer Controller
footprint ESSOP10
pins: 0 GND (power), 1 V49 (power), 2 PB7 (io), 3 CCIN (io), 4 PA0 (io), 5 CCO2 (io), 6 CCO1 (io), 7 HVOD2 (io), 8 HVOD1 (io), 9 HVCP (io), 10 VBUS (power)

## CH9241T
designator U?
RISC-V MCU & USB PD & Type-C & Fast Charge Power Consumer Controller
footprint QFN32_4X4
pins: 0 GND (power), 1 ISP2 (in), 2 DAT_EN (out), 3 DAT_SEL (out), 4 OD1 (out), 5 OD2 (out), 6 ADC_VDC (in), 7 ADC_VIN (in), 8 OD3 (out), 9 LED2 (out), 10 GND (power), 11 LED1 (out), 12 VDD5 (power), 13 DCEN (out), 14 GND (power), 15 PB11 (out), 16 VDD5 (power), 17 BST1 (out), 18 BST2 (out), 19 VDD5 (power), 20 HVIO (out), 21 VDD33 (power), 22 VHV (power), 23 CCIN (io), 24 CCO3 (io), 25 CCO1 (io), 26 CCO2 (io), 27 PB0 (io), 28 PB1 (io), 29 FB1 (in), 30 FB2 (in), 31 ISN1 (in), 32 ISP1 (in)

## CH9245F
designator U?
RISC-V MCU & USB PD & Type-C & Fast Charge Power Consumer Controller
footprint QFN32_4X4
pins: 0 GND (power), 1 FB (io), 2 PA1 (io), 3 CC2R (io), 4 CCL3 (io), 5 CCL4 (io), 6 CCGND (power), 7 CC4R (io), 8 CC3R (io), 9 HVOD2 (io), 10 HVOD1 (io), 11 HVCP (out), 12 HVOD3 (io), 13 VBUS (power), 14 V49 (power), 15 S1C (io), 16 S2C (io), 17 DC (io), 18 S1B (io), 19 S2B (io), 20 DB (io), 21 PA11/SCL (io), 22 PA12/SDA (io), 23 PA4 (io), 24 PA5 (io), 25 PA6 (io), 26 PA7/A1 (io), 27 PA8/A2 (io), 28 PB8 (io), 29 PB7 (io), 30 ISP (io), 31 PA15 (io), 32 CC1R (io)

## CH9245X
designator U?
RISC-V MCU & USB PD & Type-C & Fast Charge Power Consumer Controller
footprint QFN20_3X3
pins: 0 GND (power), 1 PA2 (io), 2 VHV (power), 3 PB3H (io), 4 PB4H (io), 5 PA3 (io), 6 PA11/A4 (io), 7 PA12/A5 (io), 8 PA4 (io), 9 PA5 (io), 10 PA6/A0 (io), 11 PA7/A1 (io), 12 PB8 (io), 13 PB7/A7 (io), 14 ISP (io), 15 CC1R (io), 16 FB (io), 17 PA1/A13 (io), 18 CC2 (io), 19 CC3R (io), 20 VDD (power)

## CH9317E
designator U1
Auxiliary Configuration for CH317L
footprint MSOP10
pins: 1 MDC/IN2 (io), 2 MDIO (io), 3 UD+ (io), 4 UD- (io), 5 IN1 (in), 6 IN0 (in), 7 RSTO (out), 8 GND (power), 9 VCC (power), 10 V33 (power)

## CH9325
designator U?
USB HID to TTL Serial / UART
footprint SOP16
pins: 1 RSTI (in), 2 TXD (out), 3 RXD (in), 4 PA2 (out), 5 V3 (power), 6 UD+ (io), 7 UD- (io), 8 GND (power), 9 XI (in), 10 XO (out), 11 PB3 (io), 12 PB5 (io), 13 PB7 (io), 14 PC3 (io), 15 VCC (power), 16 ACT# (out)

## CH9326G
designator U?
HID USB to UART Bridge, TTL Serial
footprint SOP16
pins: 1 RSTI (in), 2 TXD (io), 3 RXD (io), 4 T_LED (io), 5 V3 (power), 6 UD+ (io), 7 UD- (io), 8 GND (power), 9 XI (in), 10 XO (out), 11 IO2 (io), 12 IO1 (io), 13 IO4 (io), 14 IO3 (io), 15 VCC (power), 16 ACT# (io)

## CH9326S
designator U?
HID USB to UART Bridge, TTL Serial
footprint SOP28
pins: 1 ACT# (io), 2 RSTI (in), 3 IO5, 4 IO6, 5 TXD, 6 RXD, 7 T_LED, 8 IO7, 9 V3, 10 UD+, 11 UD-, 12 GND, 13 XI, 14 XO, 15 IO8, 16 IO9, 17 IO10, 18 IO2, 19 IO11, 20 IO1, 21 IO4, 22 IO3, 23 IO12, 24 IO13, 25 IO14, 26 IO15, 27 IO16, 28 VCC

## CH9327
designator U2
USB to SPI
footprint SOP16
pins: 1 CS2 (out), 2 CS0 (out), 3 MOSI (out), 4 MISO (in), 5 SCK (out), 6 RST (in), 7 NC, 8 NC, 9 CS1 (out), 10 CS4 (out), 11 NC, 12 UD+ (io), 13 UD- (io), 14 GND (power), 15 VCC (power), 16 V33 (power)

## CH9328
designator U?
UART to USB Keyboard
footprint SOP16
pins: 1 RSTI (in), 2 TXD (out), 3 RXD (in), 4 T_LED (out), 5 V3 (power), 6 UD+ (io), 7 UD- (io), 8 GND (power), 9 XI (in), 10 XO (out), 11 IO2 (io), 12 IO1 (io), 13 IO4 (io), 14 IO3 (io), 15 VCC (power), 16 ACT# (out)

## CH9329
designator U?
UART to USB HID Device
footprint SOP16
pins: 1 ACT# (out), 2 MODE0 (in), 3 MODE1 (in), 4 CFG0 (in), 5 CFG1 (in), 6 RST (in), 7 TXD (out), 8 RXD (in), 9 UP (out), 10 DEF (in), 11 SET (in), 12 UD+ (io), 13 UD- (io), 14 GND (power), 15 VCC (power), 16 V33 (power)

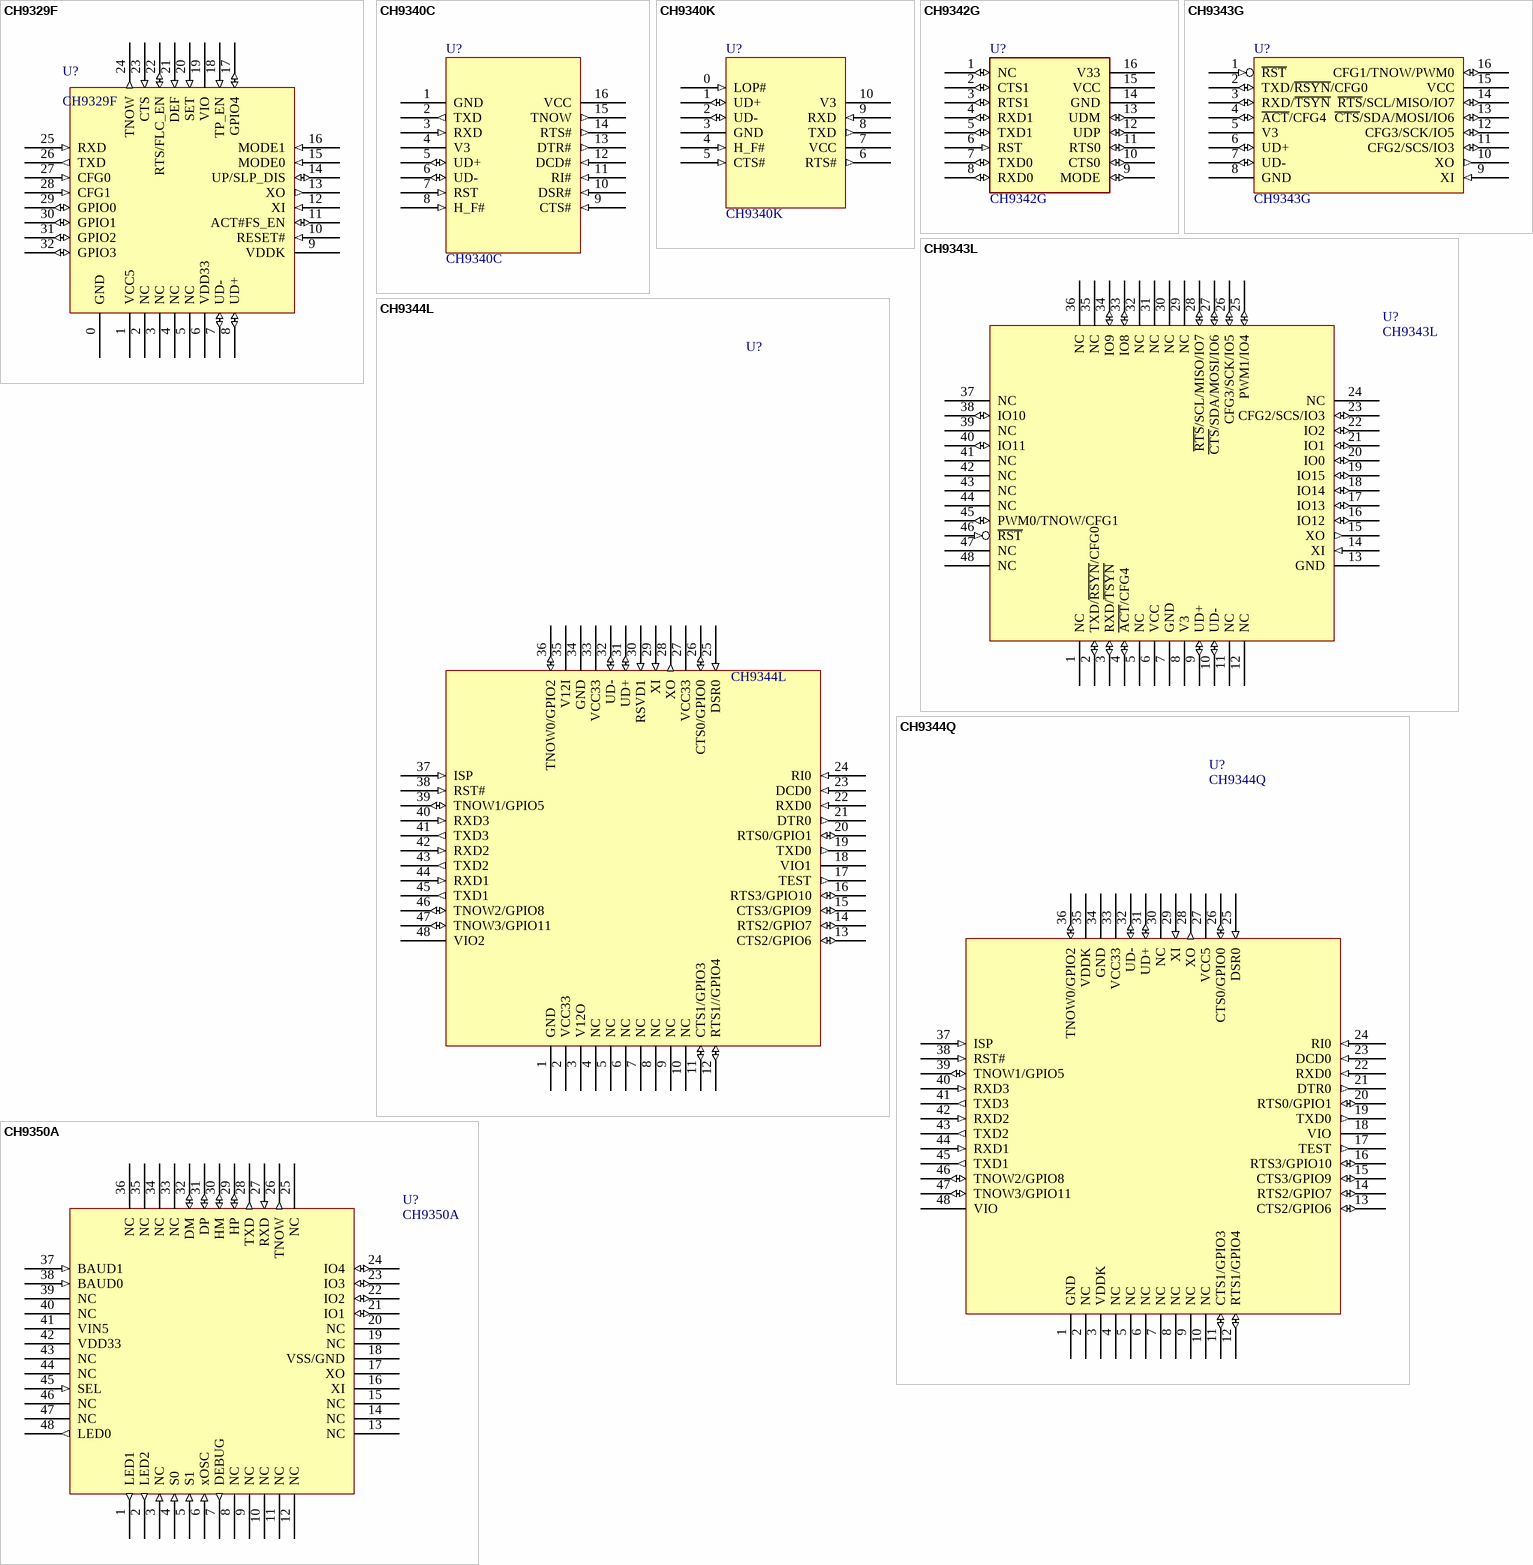
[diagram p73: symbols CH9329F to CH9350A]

## CH9329F
designator U?
TTL serial / UART to USB keyboard & USB mouse
footprint QFN32_4X4
pins: 0 GND (power), 1 VCC5 (power), 2 NC, 3 NC, 4 NC, 5 NC, 6 VDD33 (power), 7 UD- (io), 8 UD+ (io), 9 VDDK (power), 10 RESET# (in), 11 ACT#FS_EN (io), 12 XI (in), 13 XO (out), 14 UP/SLP_DIS (io), 15 MODE0 (in), 16 MODE1 (in), 17 GPIO4 (io), 18 TP_EN (in), 19 VIO (power), 20 SET (in), 21 DEF (in), 22 RTS/FLC_EN (io), 23 CTS (in), 24 TNOW (out), 25 RXD (in), 26 TXD (out), 27 CFG0 (in), 28 CFG1 (in), 29 GPIO0 (io), 30 GPIO1 (io), 31 GPIO2 (io), 32 GPIO3 (io)

## CH9340C
designator U?
USB CDC to TTL Serial / UART
footprint SOP16
pins: 1 GND (power), 2 TXD (out), 3 RXD (in), 4 V3 (power), 5 UD+ (io), 6 UD- (io), 7 RST (in), 8 H_F# (in), 9 CTS# (in), 10 DSR# (in), 11 RI# (in), 12 DCD# (in), 13 DTR# (out), 14 RTS# (out), 15 TNOW (out), 16 VCC (power)

## CH9340K
designator U?
USB CDC to TTL Serial / UART
footprint ESSOP10
pins: 0 LOP# (in), 1 UD+ (io), 2 UD- (io), 3 GND (power), 4 H_F# (in), 5 CTS# (in), 6 RTS# (out), 7 VCC (power), 8 TXD (out), 9 RXD (in), 10 V3 (power)

## CH9342G
designator U?
USB to dual TTL Serial / 2*UART
footprint SOP16
pins: 1 NC (io), 2 CTS1 (io), 3 RTS1 (io), 4 RXD1 (io), 5 TXD1 (io), 6 RST (in), 7 TXD0 (io), 8 RXD0 (io), 9 MODE (io), 10 CTS0 (io), 11 RTS0 (io), 12 UDP (io), 13 UDM (io), 14 GND (power), 15 VCC (power), 16 V33 (power)

## CH9343G
designator U?
Full-Speed USB host for accessing peripheral hardware from Android platform
footprint SOP16
pins: 1 ~{RST} (in), 2 TXD/~{RSYN}/CFG0 (io), 3 RXD/~{TSYN} (io), 4 ~{ACT}/CFG4 (io), 5 V3 (power), 6 UD+ (io), 7 UD- (io), 8 GND (power), 9 XI (in), 10 XO (out), 11 CFG2/SCS/IO3 (io), 12 CFG3/SCK/IO5 (io), 13 ~{CTS}/SDA/MOSI/IO6 (io), 14 ~{RTS}/SCL/MISO/IO7 (io), 15 VCC (power), 16 CFG1/TNOW/PWM0 (io)

## CH9343L
designator U?
Full-Speed USB host for accessing peripheral hardware from Android platform
footprint LQFP48
pins: 1 NC, 2 TXD/~{RSYN}/CFG0 (io), 3 RXD/~{TSYN} (io), 4 ~{ACT}/CFG4 (io), 5 NC, 6 VCC (power), 7 GND (power), 8 V3 (power), 9 UD+ (io), 10 UD- (io), 11 NC, 12 NC, 13 GND (power), 14 XI (in), 15 XO (out), 16 IO12 (io), 17 IO13 (io), 18 IO14 (io), 19 IO15 (io), 20 IO0 (io), 21 IO1 (io), 22 IO2 (io), 23 CFG2/SCS/IO3 (io), 24 NC, 25 PWM1/IO4 (io), 26 CFG3/SCK/IO5 (io), 27 ~{CTS}/SDA/MOSI/IO6 (io), 28 ~{RTS}/SCL/MISO/IO7 (io), 29 NC, 30 NC, 31 NC, 32 NC, 33 IO8 (io), 34 IO9 (io), 35 NC, 36 NC, 37 NC, 38 IO10 (io), 39 NC, 40 IO11 (io), 41 NC, 42 NC, 43 NC, 44 NC, 45 PWM0/TNOW/CFG1 (io), 46 ~{RST} (in), 47 NC, 48 NC

## CH9344L
designator U?
USB high-speed to quad TTL Serial / UART
footprint LQFP48
pins: 1 GND (power), 2 VCC33 (power), 3 V12O (power), 4 NC, 5 NC, 6 NC, 7 NC, 8 NC, 9 NC, 10 NC, 11 CTS1/GPIO3 (io), 12 RTS1//GPIO4 (io), 13 CTS2/GPIO6 (io), 14 RTS2/GPIO7 (io), 15 CTS3/GPIO9 (io), 16 RTS3/GPIO10 (io), 17 TEST (out), 18 VIO1 (power), 19 TXD0 (out), 20 RTS0/GPIO1 (io), 21 DTR0 (out), 22 RXD0 (in), 23 DCD0 (in), 24 RI0 (in), 25 DSR0 (in), 26 CTS0/GPIO0 (io), 27 VCC33 (power), 28 XO (out), 29 XI (in), 30 RSVD1 (in), 31 UD+ (io), 32 UD- (io), 33 VCC33 (power), 34 GND (power), 35 V12I (power), 36 TNOW0/GPIO2 (io), 37 ISP (in), 38 RST# (in), 39 TNOW1/GPIO5 (io), 40 RXD3 (in), 41 TXD3 (out), 42 RXD2 (in), 43 TXD2 (out), 44 RXD1 (in), 45 TXD1 (out), 46 TNOW2/GPIO8 (io), 47 TNOW3/GPIO11 (io), 48 VIO2 (power)

## CH9344Q
designator U?
USB high-speed to quad TTL Serial / UART
footprint LQFP48
pins: 1 GND (power), 2 NC, 3 VDDK (power), 4 NC, 5 NC, 6 NC, 7 NC, 8 NC, 9 NC, 10 NC, 11 CTS1/GPIO3 (io), 12 RTS1/GPIO4 (io), 13 CTS2/GPIO6 (io), 14 RTS2/GPIO7 (io), 15 CTS3/GPIO9 (io), 16 RTS3/GPIO10 (io), 17 TEST (out), 18 VIO (power), 19 TXD0 (out), 20 RTS0/GPIO1 (io), 21 DTR0 (out), 22 RXD0 (in), 23 DCD0 (in), 24 RI0 (in), 25 DSR0 (in), 26 CTS0/GPIO0 (io), 27 VCC5 (power), 28 XO (out), 29 XI (in), 30 NC, 31 UD+ (io), 32 UD- (io), 33 VCC33 (power), 34 GND (power), 35 VDDK (power), 36 TNOW0/GPIO2 (io), 37 ISP (in), 38 RST# (in), 39 TNOW1/GPIO5 (io), 40 RXD3 (in), 41 TXD3 (out), 42 RXD2 (in), 43 TXD2 (out), 44 RXD1 (in), 45 TXD1 (out), 46 TNOW2/GPIO8 (io), 47 TNOW3/GPIO11 (io), 48 VIO (power)

## CH9350A
designator U?
USB keyboard & USB mouse to TTL serial / UART
footprint LQFP48
pins: 1 LED1 (out), 2 LED2 (out), 3 NC (in), 4 S0 (in), 5 S1 (in), 6 xOSC (in), 7 DEBUG (out), 8 NC, 9 NC, 10 NC, 11 NC, 12 NC, 13 NC, 14 NC, 15 NC, 16 XI, 17 XO, 18 VSS/GND, 19 NC, 20 NC, 21 IO1 (io), 22 IO2 (io), 23 IO3 (io), 24 IO4 (io), 25 NC, 26 TNOW (out), 27 RXD (in), 28 TXD (out), 29 HP (io), 30 HM (io), 31 DP (io), 32 DM (io), 33 NC, 34 NC, 35 NC, 36 NC, 37 BAUD1 (in), 38 BAUD0 (in), 39 NC, 40 NC, 41 VIN5, 42 VDD33, 43 NC, 44 NC, 45 SEL (in), 46 NC, 47 NC, 48 LED0 (out)

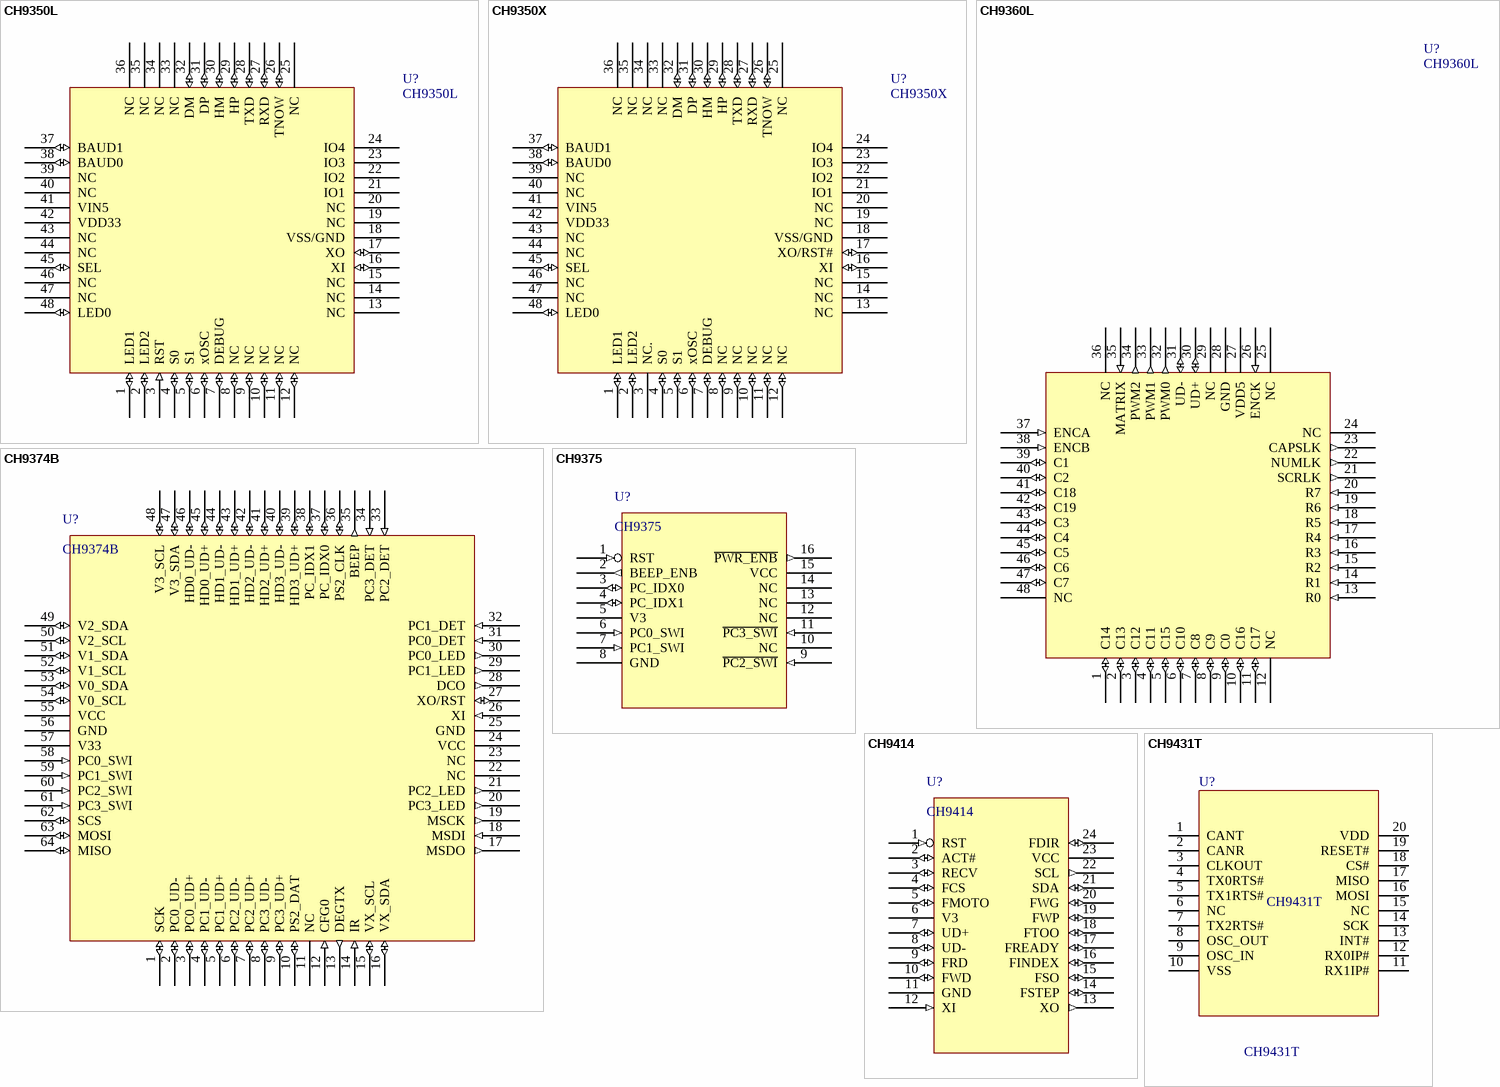
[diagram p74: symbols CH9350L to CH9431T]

## CH9350L
designator U?
USB keyboard & USB mouse to TTL serial / UART
footprint LQFP48
pins: 1 LED1 (io), 2 LED2 (io), 3 RST (in), 4 S0 (io), 5 S1 (io), 6 xOSC (io), 7 DEBUG (io), 8 NC (io), 9 NC (io), 10 NC (io), 11 NC (io), 12 NC (io), 13 NC, 14 NC, 15 NC, 16 XI (io), 17 XO (io), 18 VSS/GND (power), 19 NC, 20 NC, 21 IO1, 22 IO2, 23 IO3, 24 IO4, 25 NC, 26 TNOW (io), 27 RXD (io), 28 TXD (io), 29 HP (io), 30 HM (io), 31 DP (io), 32 DM (io), 33 NC, 34 NC, 35 NC, 36 NC, 37 BAUD1 (io), 38 BAUD0 (io), 39 NC, 40 NC, 41 VIN5 (power), 42 VDD33 (power), 43 NC, 44 NC, 45 SEL (io), 46 NC, 47 NC, 48 LED0 (io)

## CH9350X
designator U?
USB keyboard & USB mouse to TTL serial / UART
footprint LQFP48
pins: 1 LED1 (io), 2 LED2 (io), 3 NC., 4 S0 (io), 5 S1 (io), 6 xOSC (io), 7 DEBUG (io), 8 NC (io), 9 NC (io), 10 NC (io), 11 NC (io), 12 NC (io), 13 NC, 14 NC, 15 NC, 16 XI (io), 17 XO/RST# (io), 18 VSS/GND (power), 19 NC, 20 NC, 21 IO1, 22 IO2, 23 IO3, 24 IO4, 25 NC, 26 TNOW (io), 27 RXD (io), 28 TXD (io), 29 HP (io), 30 HM (io), 31 DP (io), 32 DM (io), 33 NC, 34 NC, 35 NC, 36 NC, 37 BAUD1 (io), 38 BAUD0 (io), 39 NC, 40 NC, 41 VIN5 (power), 42 VDD33 (power), 43 NC, 44 NC, 45 SEL (io), 46 NC, 47 NC, 48 LED0 (io)

## CH9360L
designator U?
USB keyboard controller
footprint LQFP48
pins: 1 C14 (io), 2 C13 (io), 3 C12 (io), 4 C11 (io), 5 C15 (io), 6 C10 (io), 7 C8 (io), 8 C9 (io), 9 C0 (io), 10 C16 (io), 11 C17 (io), 12 NC, 13 R0 (in), 14 R1 (in), 15 R2 (in), 16 R3 (in), 17 R4 (in), 18 R5 (in), 19 R6 (in), 20 R7 (in), 21 SCRLK (out), 22 NUMLK (out), 23 CAPSLK (out), 24 NC, 25 NC, 26 ENCK (in), 27 VDD5 (power), 28 GND (power), 29 NC, 30 UD+ (io), 31 UD- (io), 32 PWM0 (out), 33 PWM1 (out), 34 PWM2 (out), 35 MATRIX (in), 36 NC, 37 ENCA (in), 38 ENCB (in), 39 C1 (io), 40 C2 (io), 41 C18 (io), 42 C19 (io), 43 C3 (io), 44 C4 (io), 45 C5 (io), 46 C6 (io), 47 C7 (io), 48 NC

## CH9374B
designator U?
4-port USB KVM Switch
footprint LQFP64
pins: 1 SCK (io), 2 PC0_UD- (io), 3 PC0_UD+ (io), 4 PC1_UD- (io), 5 PC1_UD+ (io), 6 PC2_UD- (io), 7 PC2_UD+ (io), 8 PC3_UD- (io), 9 PC3_UD+ (io), 10 PS2_DAT (io), 11 NC, 12 CFG0 (in), 13 DEGTX (out), 14 IR (in), 15 VX_SCL (io), 16 VX_SDA (io), 17 MSDO (out), 18 MSDI (in), 19 MSCK (out), 20 PC3_LED (out), 21 PC2_LED (out), 22 NC, 23 NC, 24 VCC (power), 25 GND (power), 26 XI (in), 27 XO/RST (io), 28 DCO (out), 29 PC1_LED (out), 30 PC0_LED (out), 31 PC0_DET (in), 32 PC1_DET (in), 33 PC2_DET (in), 34 PC3_DET (in), 35 BEEP (out), 36 PS2_CLK (io), 37 PC_IDX0 (io), 38 PC_IDX1 (io), 39 HD3_UD+ (io), 40 HD3_UD- (io), 41 HD2_UD+ (io), 42 HD2_UD- (io), 43 HD1_UD+ (io), 44 HD1_UD- (io), 45 HD0_UD+ (io), 46 HD0_UD- (io), 47 V3_SDA (io), 48 V3_SCL (io), 49 V2_SDA (io), 50 V2_SCL (io), 51 V1_SDA (io), 52 V1_SCL (io), 53 V0_SDA (io), 54 V0_SCL (io), 55 VCC (power), 56 GND (power), 57 V33 (power), 58 PC0_SWI (in), 59 PC1_SWI (in), 60 PC2_SWI (in), 61 PC3_SWI (in), 62 SCS (io), 63 MOSI (io), 64 MISO (io)

## CH9375
designator U?
2-port/4-port manual USB KVM switch
footprint SOP16
pins: 1 RST (in), 2 BEEP_ENB (out), 3 PC_IDX0 (io), 4 PC_IDX1 (io), 5 V3 (power), 6 PC0_SWI (in), 7 PC1_SWI (in), 8 GND (power), 9 ~{PC2_SWI} (in), 10 NC, 11 ~{PC3_SWI} (in), 12 NC, 13 NC, 14 NC, 15 VCC (power), 16 ~{PWR_ENB} (out)

## CH9414
designator U?
USB floppy drive
footprint SSOP24
pins: 1 RST (in), 2 ACT# (io), 3 RECV (io), 4 FCS (io), 5 FMOTO (io), 6 V3 (power), 7 UD+ (io), 8 UD- (io), 9 FRD (io), 10 FWD (io), 11 GND (power), 12 XI (in), 13 XO (out), 14 FSTEP (io), 15 FSO (io), 16 FINDEX (io), 17 FREADY (io), 18 FTOO (io), 19 FWP (io), 20 FWG (io), 21 SDA (io), 22 SCL (out), 23 VCC (power), 24 FDIR (io)

## CH9431T
designator U?
SPI to CAN
footprint TSSOP20 (Footprint not found)
pins: 1 CANT, 2 CANR, 3 CLKOUT, 4 TX0RTS#, 5 TX1RTS#, 6 NC, 7 TX2RTS#, 8 OSC_OUT, 9 OSC_IN, 10 VSS (power), 11 RX1IP#, 12 RX0IP#, 13 INT#, 14 SCK, 15 NC, 16 MOSI, 17 MISO, 18 CS#, 19 RESET#, 20 VDD (power)

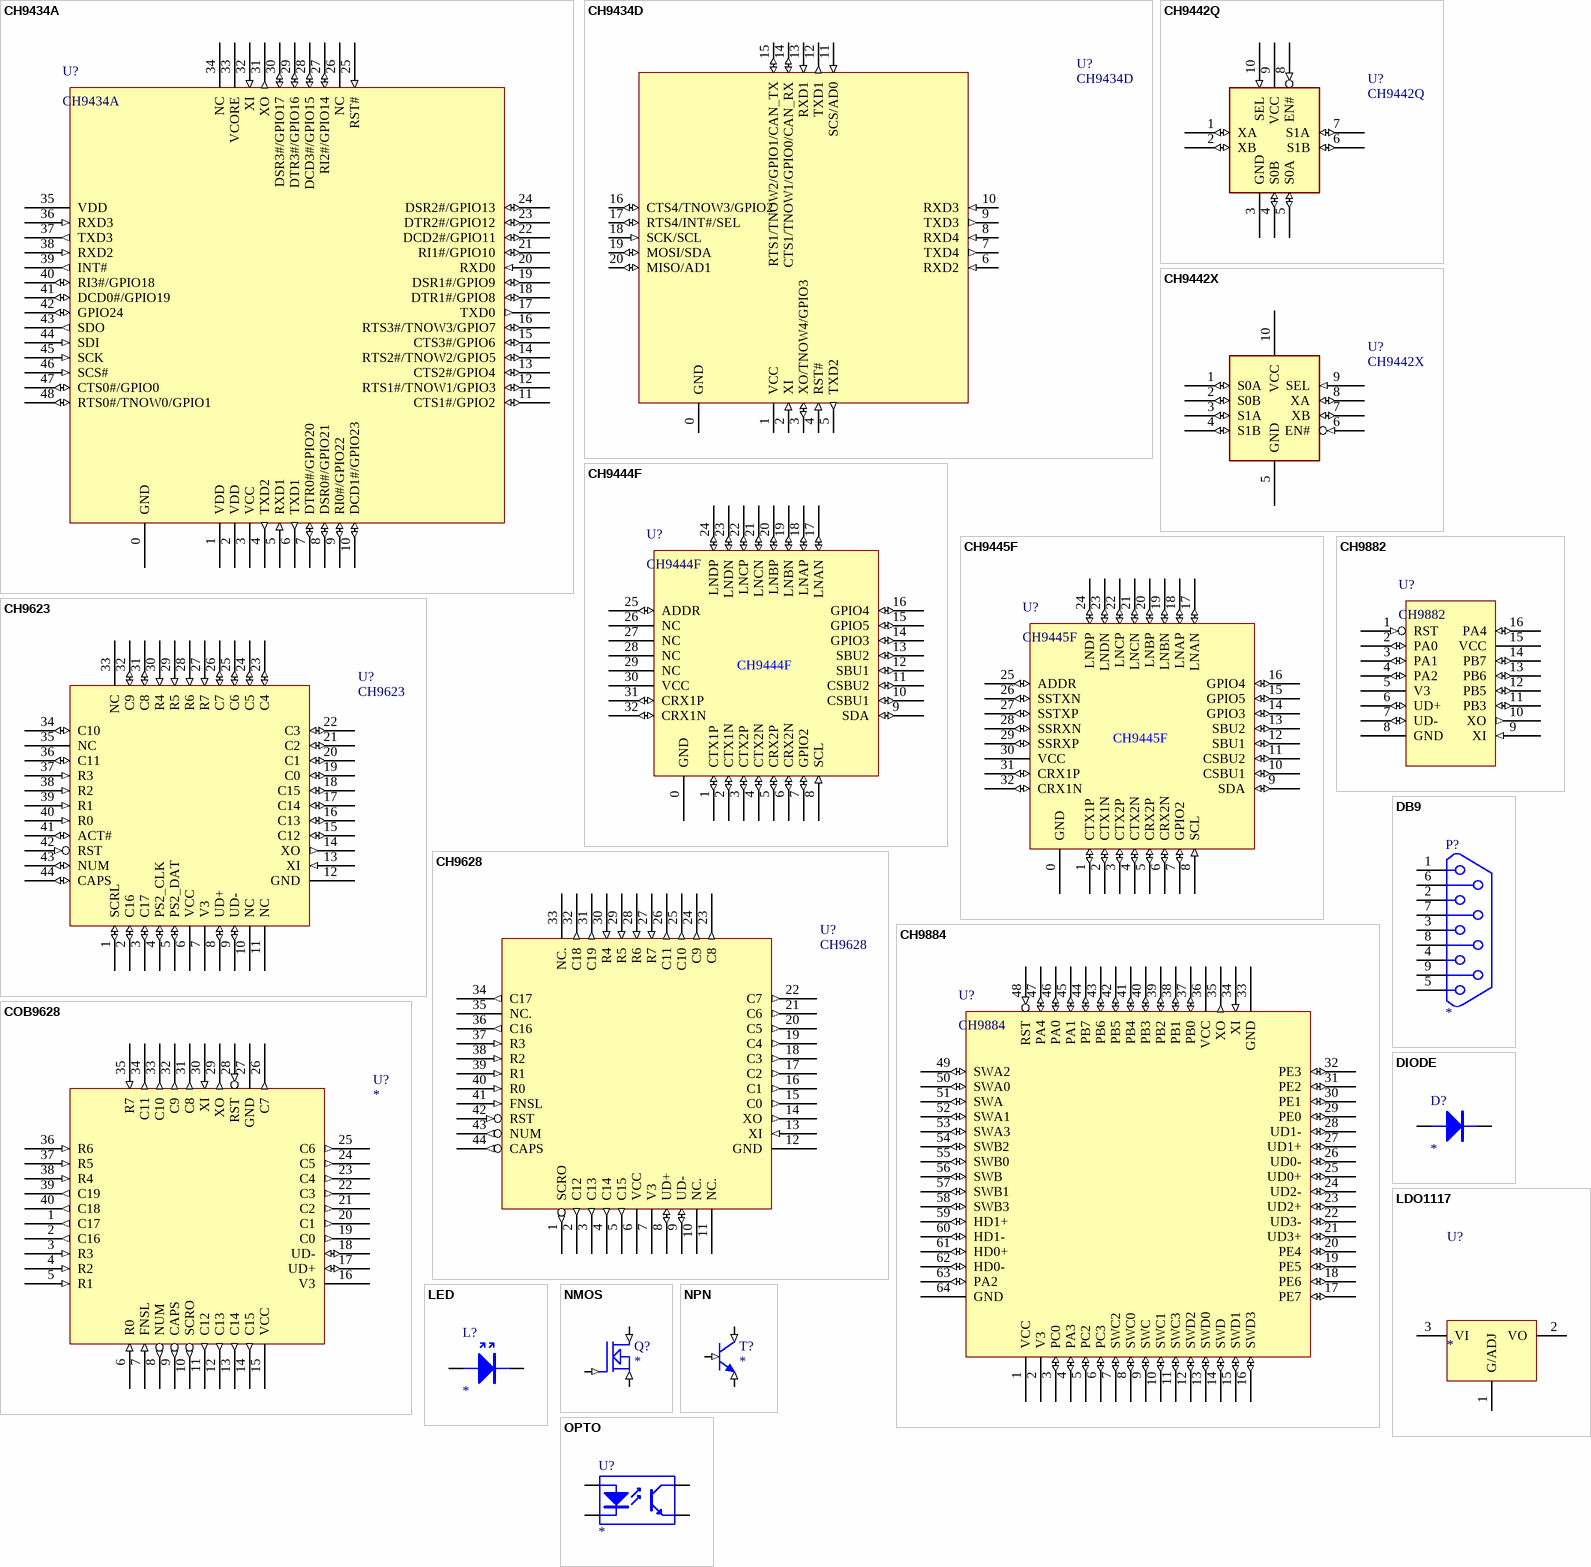
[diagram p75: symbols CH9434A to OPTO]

## CH9434A
designator U?
SPI to quad TTL Serial / 4*UART
footprint QFN48_5X5
pins: 0 GND (power), 1 VDD (power), 2 VDD (power), 3 VCC (power), 4 TXD2 (out), 5 RXD1 (in), 6 TXD1 (out), 7 DTR0#/GPIO20 (io), 8 DSR0#/GPIO21 (io), 9 RI0#/GPIO22 (io), 10 DCD1#/GPIO23 (io), 11 CTS1#/GPIO2 (io), 12 RTS1#/TNOW1/GPIO3 (io), 13 CTS2#/GPIO4 (io), 14 RTS2#/TNOW2/GPIO5 (io), 15 CTS3#/GPIO6 (io), 16 RTS3#/TNOW3/GPIO7 (io), 17 TXD0 (out), 18 DTR1#/GPIO8 (io), 19 DSR1#/GPIO9 (io), 20 RXD0 (in), 21 RI1#/GPIO10 (io), 22 DCD2#/GPIO11 (io), 23 DTR2#/GPIO12 (io), 24 DSR2#/GPIO13 (io), 25 RST# (in), 26 NC, 27 RI2#/GPIO14 (io), 28 DCD3#/GPIO15 (io), 29 DTR3#/GPIO16 (io), 30 DSR3#/GPIO17 (io), 31 XO (out), 32 XI (in), 33 VCORE (power), 34 NC, 35 VDD (power), 36 RXD3 (in), 37 TXD3 (out), 38 RXD2 (in), 39 INT# (out), 40 RI3#/GPIO18 (io), 41 DCD0#/GPIO19 (io), 42 GPIO24 (io), 43 SDO (out), 44 SDI (in), 45 SCK (in), 46 SCS# (in), 47 CTS0#/GPIO0 (io), 48 RTS0#/TNOW0/GPIO1 (io)

## CH9434D
designator U?
SPI/IIC to quad TTL Serial / UART & CAN
footprint QFN20_3X3 (Footprint not found)
pins: 0 GND (power), 1 VCC (power), 2 XI (in), 3 XO/TNOW4/GPIO3 (io), 4 RST# (in), 5 TXD2 (out), 6 RXD2 (in), 7 TXD4 (out), 8 RXD4 (in), 9 TXD3 (out), 10 RXD3 (in), 11 SCS/AD0 (in), 12 TXD1 (out), 13 RXD1 (in), 14 CTS1/TNOW1/GPIO0/CAN_RX (io), 15 RTS1/TNOW2/GPIO1/CAN_TX (io), 16 CTS4/TNOW3/GPIO2 (io), 17 RTS4/INT#/SEL (io), 18 SCK/SCL (in), 19 MOSI/SDA (io), 20 MISO/AD1 (io)

## CH9442Q
designator U?
USB Analog switch with Type-C High Voltage 28V OVP
footprint QFN10_14X18 (Footprint not found)
pins: 1 XA (io), 2 XB (io), 3 GND (power), 4 S0B (io), 5 S0A (io), 6 S1B (io), 7 S1A (io), 8 EN# (in), 9 VCC (power), 10 SEL (in)

## CH9442X
designator U?
USB Analog switch with Type-C High Voltage 28V OVP
footprint QFN10_15X2 (Footprint not found)
pins: 1 S0A (io), 2 S0B (io), 3 S1A (io), 4 S1B (io), 5 GND (power), 6 EN# (in), 7 XB (io), 8 XA (io), 9 SEL (in), 10 VCC (power)

## CH9444F
designator U?
Ultra high speed differential signal bidirectional analog switch, DP1.4 & USB3.0 & USB3.2 Gen2x2.
footprint QFN32_4X4
pins: 0 GND (power), 1 CTX1P (io), 2 CTX1N (io), 3 CTX2P (io), 4 CTX2N (io), 5 CRX2P (io), 6 CRX2N (io), 7 GPIO2 (io), 8 SCL (in), 9 SDA (io), 10 CSBU1 (io), 11 CSBU2 (io), 12 SBU1 (io), 13 SBU2 (io), 14 GPIO3 (io), 15 GPIO5 (io), 16 GPIO4 (io), 17 LNAN (io), 18 LNAP (io), 19 LNBN (io), 20 LNBP (io), 21 LNCN (io), 22 LNCP (io), 23 LNDN (io), 24 LNDP (io), 25 ADDR (io), 26 NC, 27 NC, 28 NC, 29 NC, 30 VCC (power), 31 CRX1P (io), 32 CRX1N (io)

## CH9445F
designator U?
Ultra high speed differential signal bidirectional analog switch, DP1.4 & USB3.0 & USB3.2 Gen2x2.
footprint QFN32_4X4
pins: 0 GND (power), 1 CTX1P (io), 2 CTX1N (io), 3 CTX2P (io), 4 CTX2N (io), 5 CRX2P (io), 6 CRX2N (io), 7 GPIO2 (io), 8 SCL (in), 9 SDA (io), 10 CSBU1 (io), 11 CSBU2 (io), 12 SBU1 (io), 13 SBU2 (io), 14 GPIO3 (io), 15 GPIO5 (io), 16 GPIO4 (io), 17 LNAN (io), 18 LNAP (io), 19 LNBN (io), 20 LNBP (io), 21 LNCN (io), 22 LNCP (io), 23 LNDN (io), 24 LNDP (io), 25 ADDR (io), 26 SSTXN (io), 27 SSTXP (io), 28 SSRXN (io), 29 SSRXP (io), 30 VCC (power), 31 CRX1P (io), 32 CRX1N (io)

## CH9623
designator U?
USB keyboard controller with PS2 touchpad decoder
footprint LQFP44
pins: 1 SCRL (io), 2 C16 (io), 3 C17 (io), 4 PS2_CLK (io), 5 PS2_DAT (io), 6 VCC (power), 7 V3 (power), 8 UD+ (io), 9 UD- (io), 10 NC, 11 NC, 12 GND (power), 13 XI (in), 14 XO (out), 15 C12 (io), 16 C13 (io), 17 C14 (io), 18 C15 (io), 19 C0 (io), 20 C1 (io), 21 C2 (io), 22 C3 (io), 23 C4 (io), 24 C5 (io), 25 C6 (io), 26 C7 (io), 27 R7 (in), 28 R6 (in), 29 R5 (in), 30 R4 (in), 31 C8 (io), 32 C9 (io), 33 NC, 34 C10 (io), 35 NC, 36 C11 (io), 37 R3 (in), 38 R2 (in), 39 R1 (in), 40 R0 (in), 41 ACT# (io), 42 RST (in), 43 NUM (io), 44 CAPS (io)

## CH9628
designator U?
USB keyboard controller
footprint LQFP44
pins: 1 SCRO (out), 2 C12 (out), 3 C13 (out), 4 C14 (out), 5 C15 (out), 6 VCC (power), 7 V3 (power), 8 UD+ (io), 9 UD- (io), 10 NC., 11 NC., 12 GND (power), 13 XI (in), 14 XO (out), 15 C0 (out), 16 C1 (out), 17 C2 (out), 18 C3 (out), 19 C4 (out), 20 C5 (out), 21 C6 (out), 22 C7 (out), 23 C8 (out), 24 C9 (out), 25 C10 (out), 26 C11 (out), 27 R7 (in), 28 R6 (in), 29 R5 (in), 30 R4 (in), 31 C19 (out), 32 C18 (out), 33 NC., 34 C17 (out), 35 NC., 36 C16 (out), 37 R3 (in), 38 R2 (in), 39 R1 (in), 40 R0 (in), 41 FNSL (in), 42 RST (in), 43 NUM (out), 44 CAPS (out)

## CH9882
designator U?
2-port USB sharer
footprint SOP16
pins: 1 RST (in), 2 PA0 (io), 3 PA1 (io), 4 PA2 (io), 5 V3 (power), 6 UD+ (io), 7 UD- (io), 8 GND (power), 9 XI (in), 10 XO (out), 11 PB3 (io), 12 PB5 (io), 13 PB6 (io), 14 PB7 (io), 15 VCC (power), 16 PA4 (io)

## CH9884
designator U?
4-port USB sharer
footprint LQFP64
pins: 1 VCC (power), 2 V3 (power), 3 PC0 (io), 4 PA3 (io), 5 PC2 (io), 6 PC3 (io), 7 SWC2 (io), 8 SWC0 (io), 9 SWC (io), 10 SWC1 (io), 11 SWC3 (io), 12 SWD2 (io), 13 SWD0 (io), 14 SWD (io), 15 SWD1 (io), 16 SWD3 (io), 17 PE7 (io), 18 PE6 (io), 19 PE5 (io), 20 PE4 (io), 21 UD3+ (io), 22 UD3- (io), 23 UD2+ (io), 24 UD2- (io), 25 UD0+ (io), 26 UD0- (io), 27 UD1+ (io), 28 UD1- (io), 29 PE0 (io), 30 PE1 (io), 31 PE2 (io), 32 PE3 (io), 33 GND (power), 34 XI (in), 35 XO (out), 36 VCC (power), 37 PB0 (io), 38 PB1 (io), 39 PB2 (io), 40 PB3 (io), 41 PB4 (io), 42 PB5 (io), 43 PB6 (io), 44 PB7 (io), 45 PA1 (io), 46 PA0 (io), 47 PA4 (io), 48 RST (in), 49 SWA2 (io), 50 SWA0 (io), 51 SWA (io), 52 SWA1 (io), 53 SWA3 (io), 54 SWB2 (io), 55 SWB0 (io), 56 SWB (io), 57 SWB1 (io), 58 SWB3 (io), 59 HD1+ (io), 60 HD1- (io), 61 HD0+ (io), 62 HD0- (io), 63 PA2 (io), 64 GND (power)

## COB9628
designator U?
USB keyboard controller
footprint COB40
pins: 1 C17 (out), 2 C16 (out), 3 R3 (in), 4 R2 (in), 5 R1 (in), 6 R0 (in), 7 FNSL (in), 8 NUM (out), 9 CAPS (out), 10 SCRO (out), 11 C12 (out), 12 C13 (out), 13 C14 (out), 14 C15 (out), 15 VCC (power), 16 V3 (power), 17 UD+ (io), 18 UD- (io), 19 C0 (out), 20 C1 (out), 21 C2 (out), 22 C3 (out), 23 C4 (out), 24 C5 (out), 25 C6 (out), 26 C7 (out), 27 GND (power), 28 RST (in), 29 XO (out), 30 XI (in), 31 C8 (out), 32 C9 (out), 33 C10 (out), 34 C11 (out), 35 R7 (in), 36 R6 (in), 37 R5 (in), 38 R4 (in), 39 C19 (out), 40 C18 (out)

## DB9
designator P?
footprint DB9/M
footprint DB9/F
pins: 1, 2, 3, 4, 5, 6, 7, 8, 9

## DIODE
designator D?
Diode
footprint 3216+
footprint 0805+
footprint 0603+
pins: 1 A, 2 K

## LDO1117
designator U?
LDO
footprint SOT-223
footprint SOT-23 (Footprint not found)
footprint SOT-23-3 (Footprint not found)
pins: 1 G/ADJ (power), 2 VO (power), 3 VI (power)

## LED
designator L?
LED
footprint 0805+
footprint 3216+
footprint 0603+
pins: 1 A, 2 K

## NMOS
designator Q?
N-MOSFET
footprint SOT-523
footprint SOT-23 (Footprint not found)
pins: 1 G (in), 2 S (in), 3 D (in)

## NPN
designator T?
NPN BJT
footprint SOT-23 (Footprint not found)
pins: 1 B (in), 2 E (in), 3 C (in)

## OPTO
designator U?
Optoisolator
footprint DIP4
footprint SOP4
pins: 1 A, 2 K, 3 E, 4 C

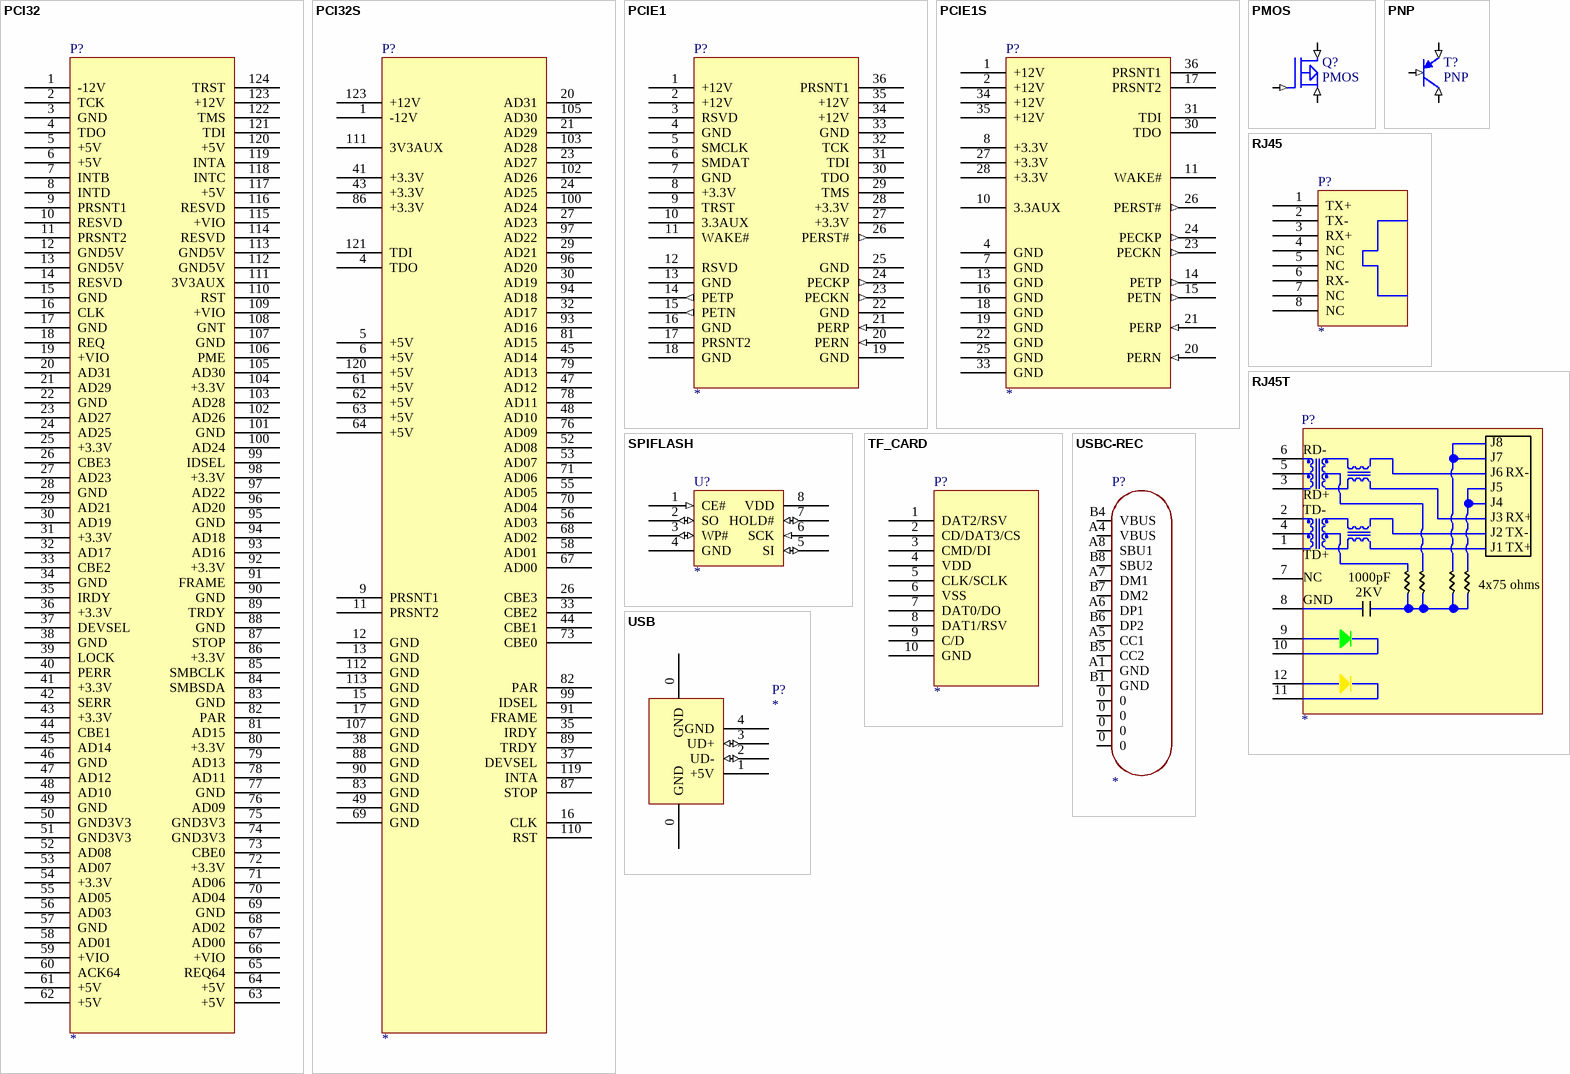
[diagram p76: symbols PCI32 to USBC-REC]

## PCI32
designator P?
32Bit PCI Bus
footprint PCI32
pins: 1 -12V, 2 TCK, 3 GND, 4 TDO, 5 +5V, 6 +5V, 7 INTB, 8 INTD, 9 PRSNT1, 10 RESVD, 11 PRSNT2, 12 GND5V, 13 GND5V, 14 RESVD, 15 GND, 16 CLK, 17 GND, 18 REQ, 19 +VIO, 20 AD31, 21 AD29, 22 GND, 23 AD27, 24 AD25, 25 +3.3V, 26 CBE3, 27 AD23, 28 GND, 29 AD21, 30 AD19, 31 +3.3V, 32 AD17, 33 CBE2, 34 GND, 35 IRDY, 36 +3.3V, 37 DEVSEL, 38 GND, 39 LOCK, 40 PERR, 41 +3.3V, 42 SERR, 43 +3.3V, 44 CBE1, 45 AD14, 46 GND, 47 AD12, 48 AD10, 49 GND, 50 GND3V3, 51 GND3V3, 52 AD08, 53 AD07, 54 +3.3V, 55 AD05, 56 AD03, 57 GND, 58 AD01, 59 +VIO, 60 ACK64, 61 +5V, 62 +5V, 63 +5V, 64 +5V, 65 REQ64, 66 +VIO, 67 AD00, 68 AD02, 69 GND, 70 AD04, 71 AD06, 72 +3.3V, 73 CBE0, 74 GND3V3, 75 GND3V3, 76 AD09, 77 GND, 78 AD11, 79 AD13, 80 +3.3V, 81 AD15, 82 PAR, 83 GND, 84 SMBSDA, 85 SMBCLK, 86 +3.3V, 87 STOP, 88 GND, 89 TRDY, 90 GND, 91 FRAME, 92 +3.3V, 93 AD16, 94 AD18, 95 GND, 96 AD20, 97 AD22, 98 +3.3V, 99 IDSEL, 100 AD24, 101 GND, 102 AD26, 103 AD28, 104 +3.3V, 105 AD30, 106 PME, 107 GND, 108 GNT, 109 +VIO, 110 RST, 111 3V3AUX, 112 GND5V, 113 GND5V, 114 RESVD, 115 +VIO, 116 RESVD, 117 +5V, 118 INTC, 119 INTA, 120 +5V, 121 TDI, 122 TMS, 123 +12V, 124 TRST

## PCI32S
designator P?
32Bit PCI Bus, simple / short card
footprint PCI32
footprint PCI32S
pins: 1 -12V, 4 TDO, 5 +5V, 6 +5V, 9 PRSNT1, 11 PRSNT2, 12 GND, 13 GND, 15 GND, 16 CLK, 17 GND, 20 AD31, 21 AD29, 23 AD27, 24 AD25, 26 CBE3, 27 AD23, 29 AD21, 30 AD19, 32 AD17, 33 CBE2, 35 IRDY, 37 DEVSEL, 38 GND, 41 +3.3V, 43 +3.3V, 44 CBE1, 45 AD14, 47 AD12, 48 AD10, 49 GND, 52 AD08, 53 AD07, 55 AD05, 56 AD03, 58 AD01, 61 +5V, 62 +5V, 63 +5V, 64 +5V, 67 AD00, 68 AD02, 69 GND, 70 AD04, 71 AD06, 73 CBE0, 76 AD09, 78 AD11, 79 AD13, 81 AD15, 82 PAR, 83 GND, 86 +3.3V, 87 STOP, 88 GND, 89 TRDY, 90 GND, 91 FRAME, 93 AD16, 94 AD18, 96 AD20, 97 AD22, 99 IDSEL, 100 AD24, 102 AD26, 103 AD28, 105 AD30, 107 GND, 110 RST, 111 3V3AUX, 112 GND, 113 GND, 119 INTA, 120 +5V, 121 TDI, 123 +12V

## PCIE1
designator P?
PCIe Bus 1X
footprint PCIE1
pins: 1 +12V (power), 2 +12V (power), 3 RSVD, 4 GND (power), 5 SMCLK, 6 SMDAT, 7 GND (power), 8 +3.3V (power), 9 TRST, 10 3.3AUX (power), 11 WAKE#, 12 RSVD, 13 GND (power), 14 PETP (out), 15 PETN (out), 16 GND (power), 17 PRSNT2, 18 GND (power), 19 GND (power), 20 PERN (in), 21 PERP (in), 22 GND (power), 23 PECKN (out), 24 PECKP (out), 25 GND (power), 26 PERST# (out), 27 +3.3V (power), 28 +3.3V (power), 29 TMS, 30 TDO, 31 TDI, 32 TCK, 33 GND (power), 34 +12V (power), 35 +12V (power), 36 PRSNT1

## PCIE1S
designator P?
PCIe Bus 1X, simple
footprint PCIE1
pins: 1 +12V (power), 2 +12V (power), 4 GND (power), 7 GND (power), 8 +3.3V (power), 10 3.3AUX (power), 11 WAKE#, 13 GND (power), 14 PETP (out), 15 PETN (out), 16 GND (power), 17 PRSNT2, 18 GND (power), 19 GND (power), 20 PERN (in), 21 PERP (in), 22 GND (power), 23 PECKN (out), 24 PECKP (out), 25 GND (power), 26 PERST# (out), 27 +3.3V (power), 28 +3.3V (power), 30 TDO, 31 TDI, 33 GND (power), 34 +12V (power), 35 +12V (power), 36 PRSNT1

## PMOS
designator Q?
P-MOSFET
footprint SOT-523
footprint SOT-23 (Footprint not found)
pins: 1 G (in), 2 S (in), 3 D (in)

## PNP
designator T?
PNP BJT
footprint SOT-23 (Footprint not found)
pins: 1 B (in), 2 E (in), 3 C (in)

## RJ45
designator P?
RJ45 for Ethernet
footprint RJ45
pins: 1 TX+, 2 TX-, 3 RX+, 4 NC, 5 NC, 6 RX-, 7 NC, 8 NC

## RJ45T
designator P?
RJ45 for Ethernet with Isolation Transformer
footprint RJ45T
footprint RJ45A
pins: 1, 2, 3, 4, 5, 6, 7, 8, 9, 10, 11, 12

## SPIFLASH
designator U?
SPI Flash ROM
footprint SOP8
pins: 1 CE# (in), 2 SO (io), 3 WP# (io), 4 GND (power), 5 SI (io), 6 SCK (in), 7 HOLD# (io), 8 VDD (power)

## TF_CARD
designator P?
TF card interface
footprint TF_CARD
pins: 1 DAT2/RSV, 2 CD/DAT3/CS, 3 CMD/DI, 4 VDD, 5 CLK/SCLK, 6 VSS, 7 DAT0/DO, 8 DAT1/RSV, 9 C/D, 10 GND

## USB
designator P?
USB Port
footprint USBAF
footprint USBB
pins: 0 GND (power), 0 GND (power), 1 +5V (power), 2 UD- (io), 3 UD+ (io), 4 GND (power)

## USBC-REC
designator P?
USB Type-C USB
footprint TYPE-C-Receptacle-2.0
pins: 0, 0, 0, 0, A1 GND, A4 VBUS, A5 CC1, A6 DP1, A7 DM1, A8 SBU1, B1 GND, B4 VBUS, B5 CC2, B6 DP2, B7 DM2, B8 SBU2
